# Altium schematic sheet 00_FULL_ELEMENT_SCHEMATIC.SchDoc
size 3600 x 2000 mm
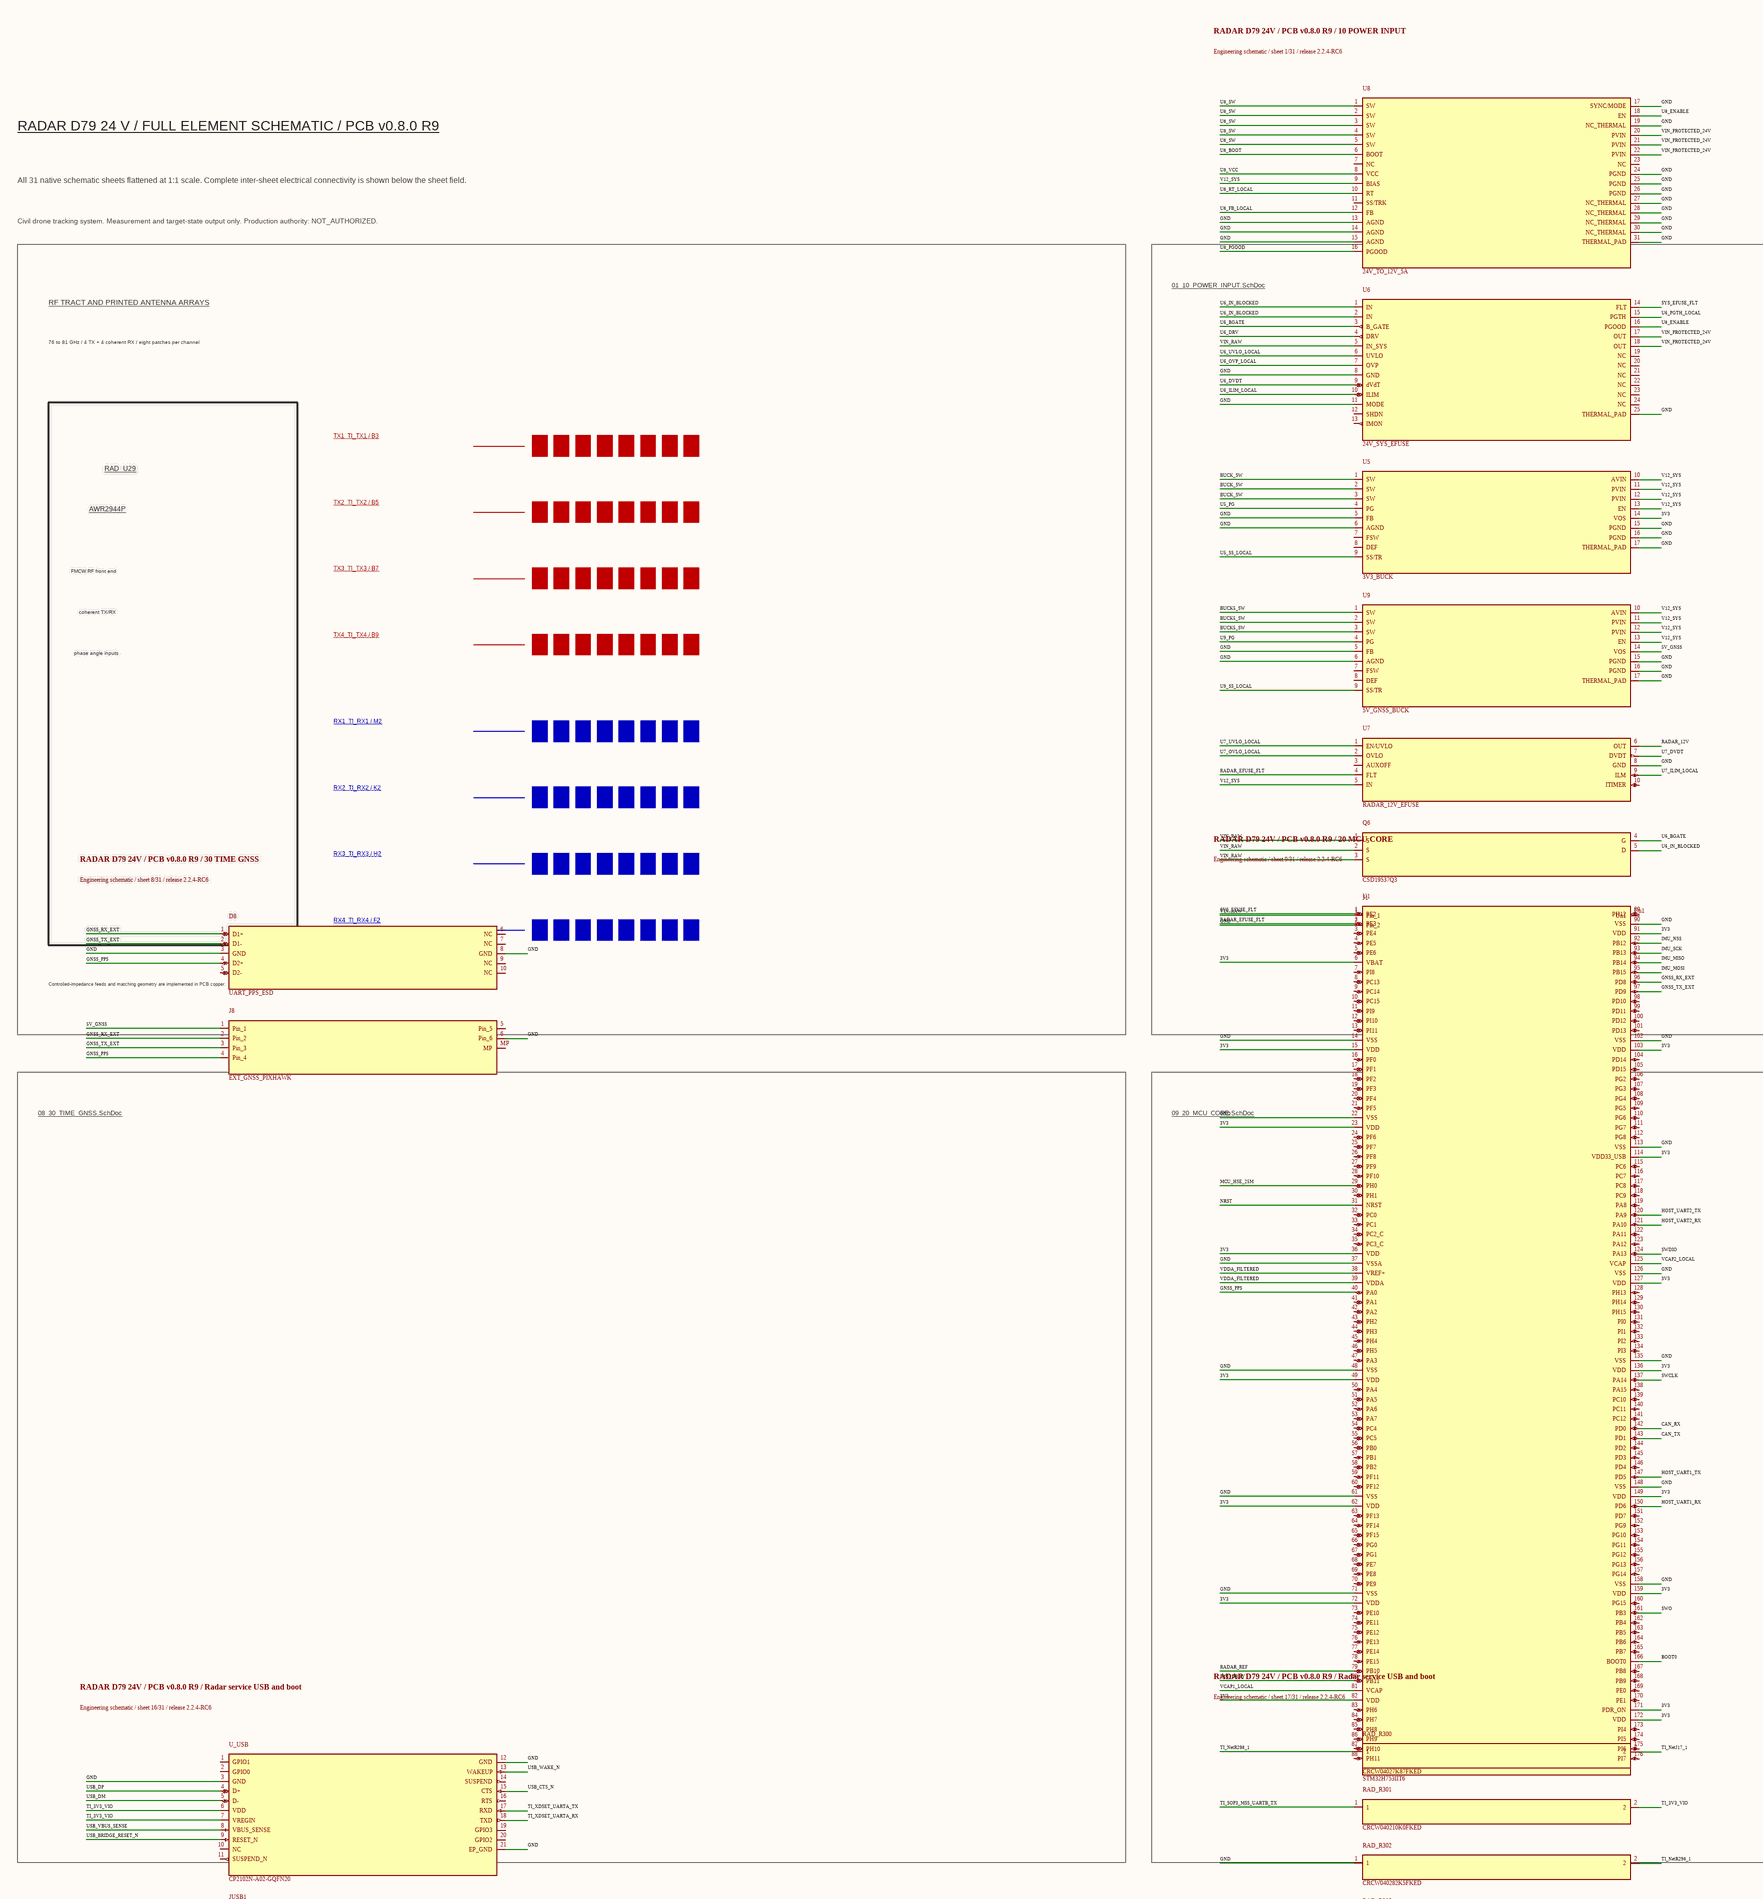
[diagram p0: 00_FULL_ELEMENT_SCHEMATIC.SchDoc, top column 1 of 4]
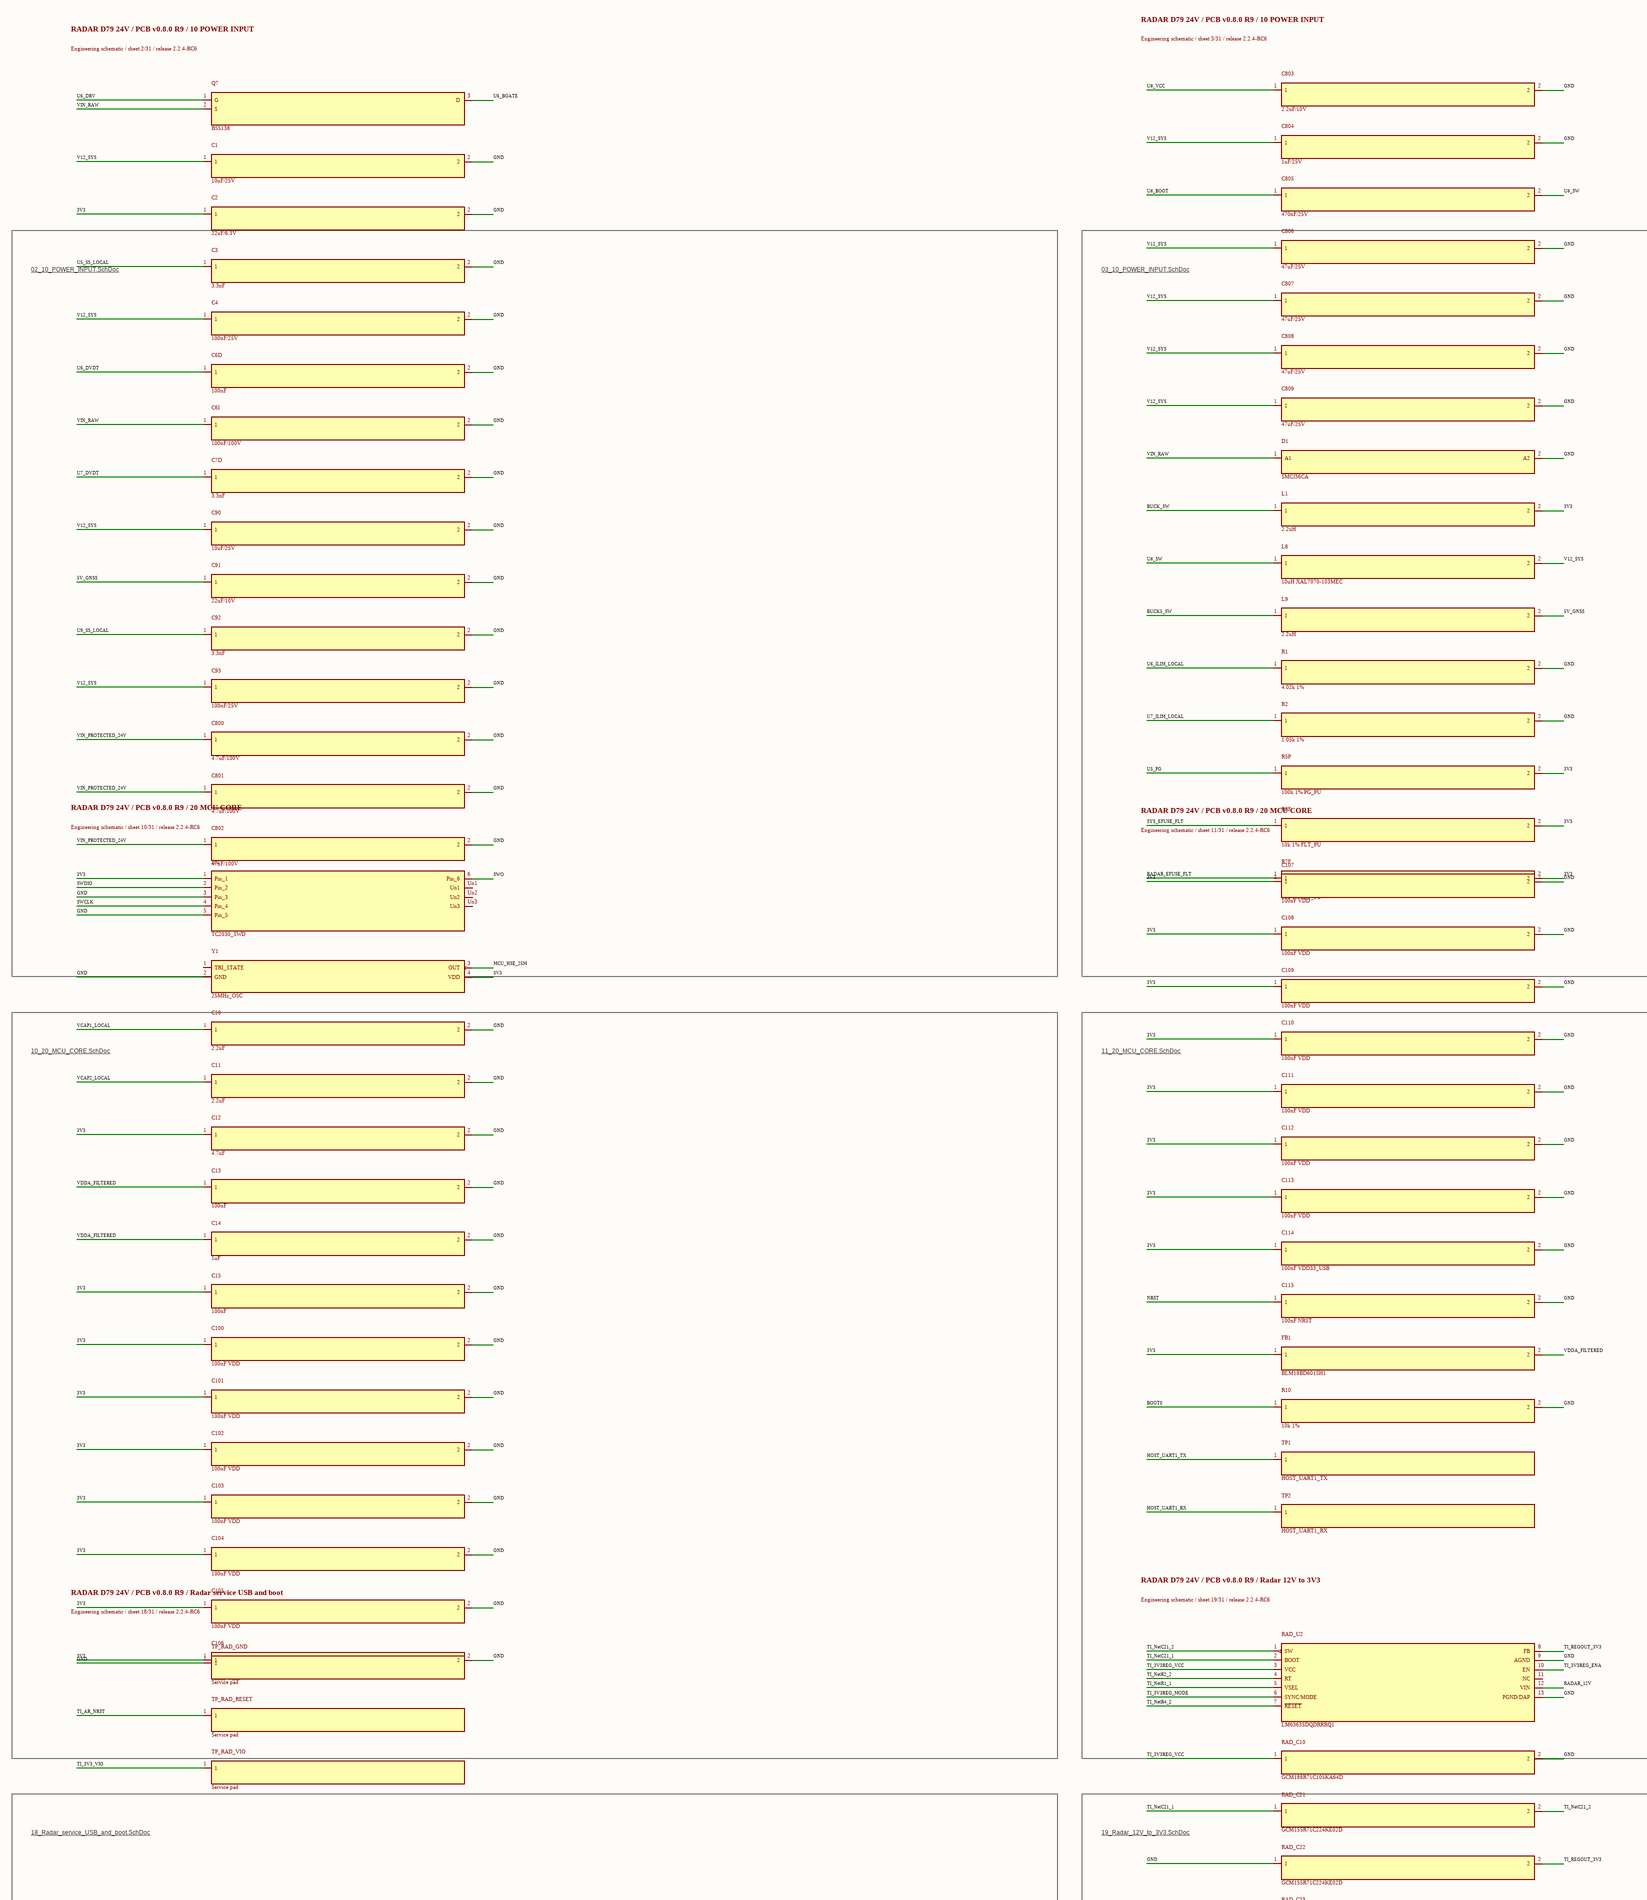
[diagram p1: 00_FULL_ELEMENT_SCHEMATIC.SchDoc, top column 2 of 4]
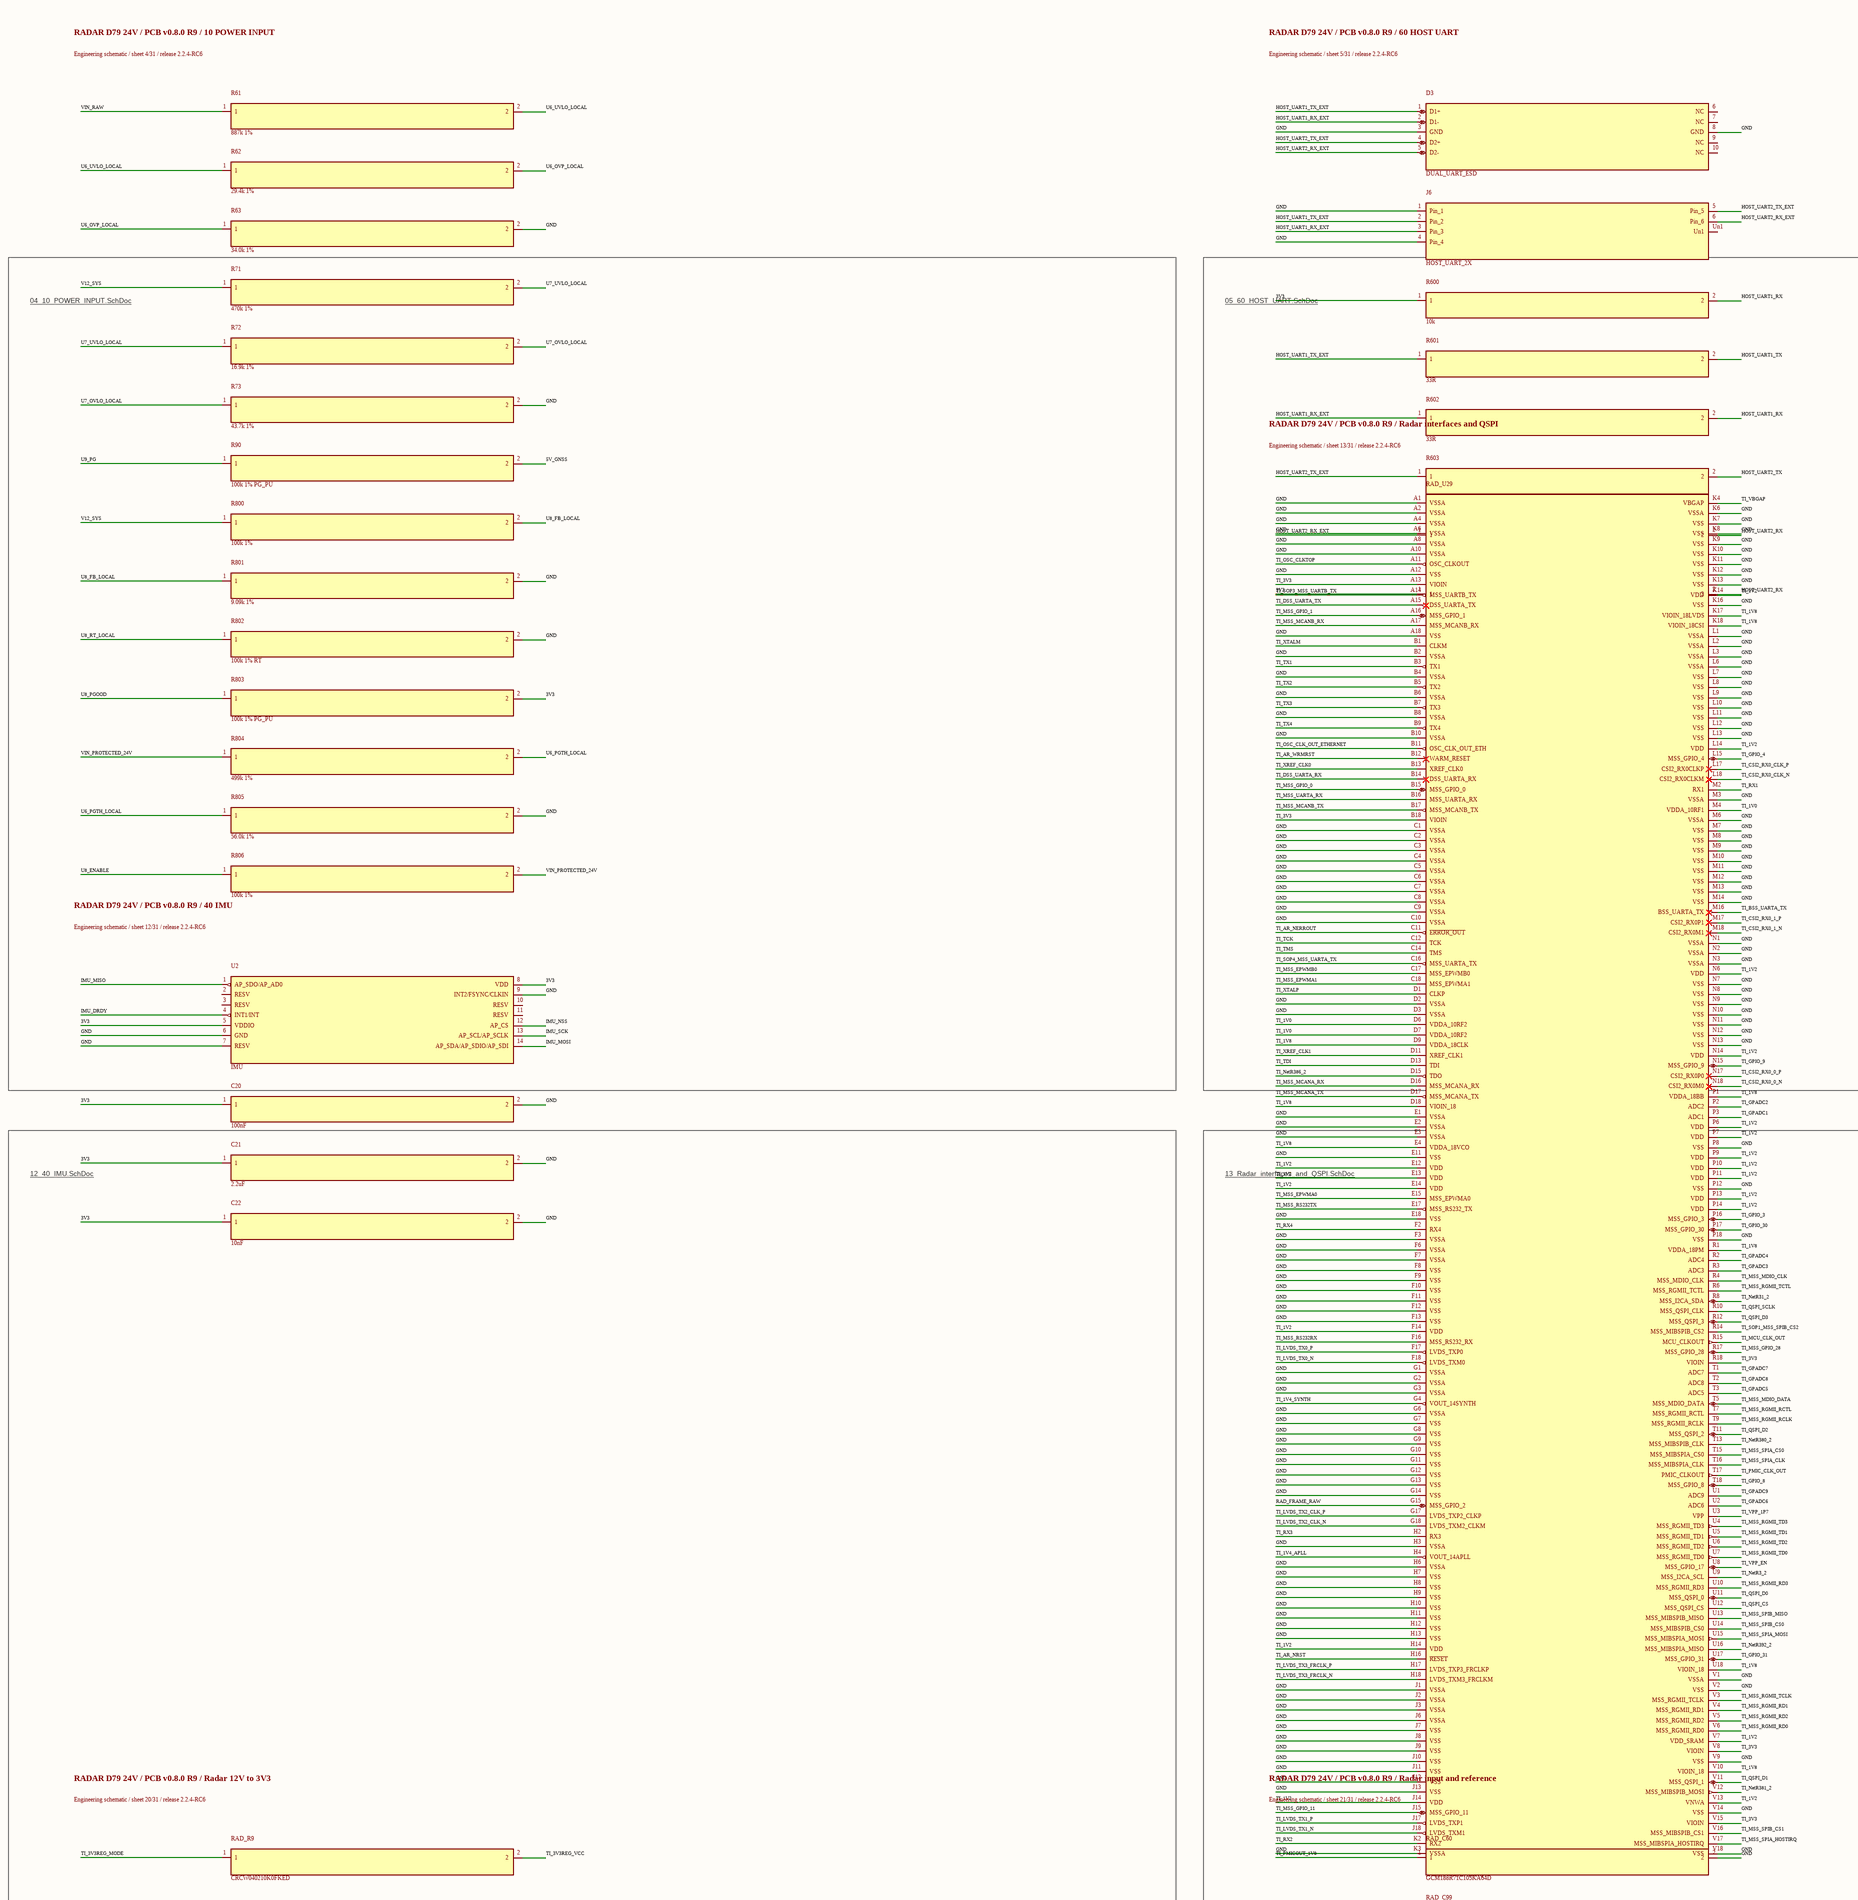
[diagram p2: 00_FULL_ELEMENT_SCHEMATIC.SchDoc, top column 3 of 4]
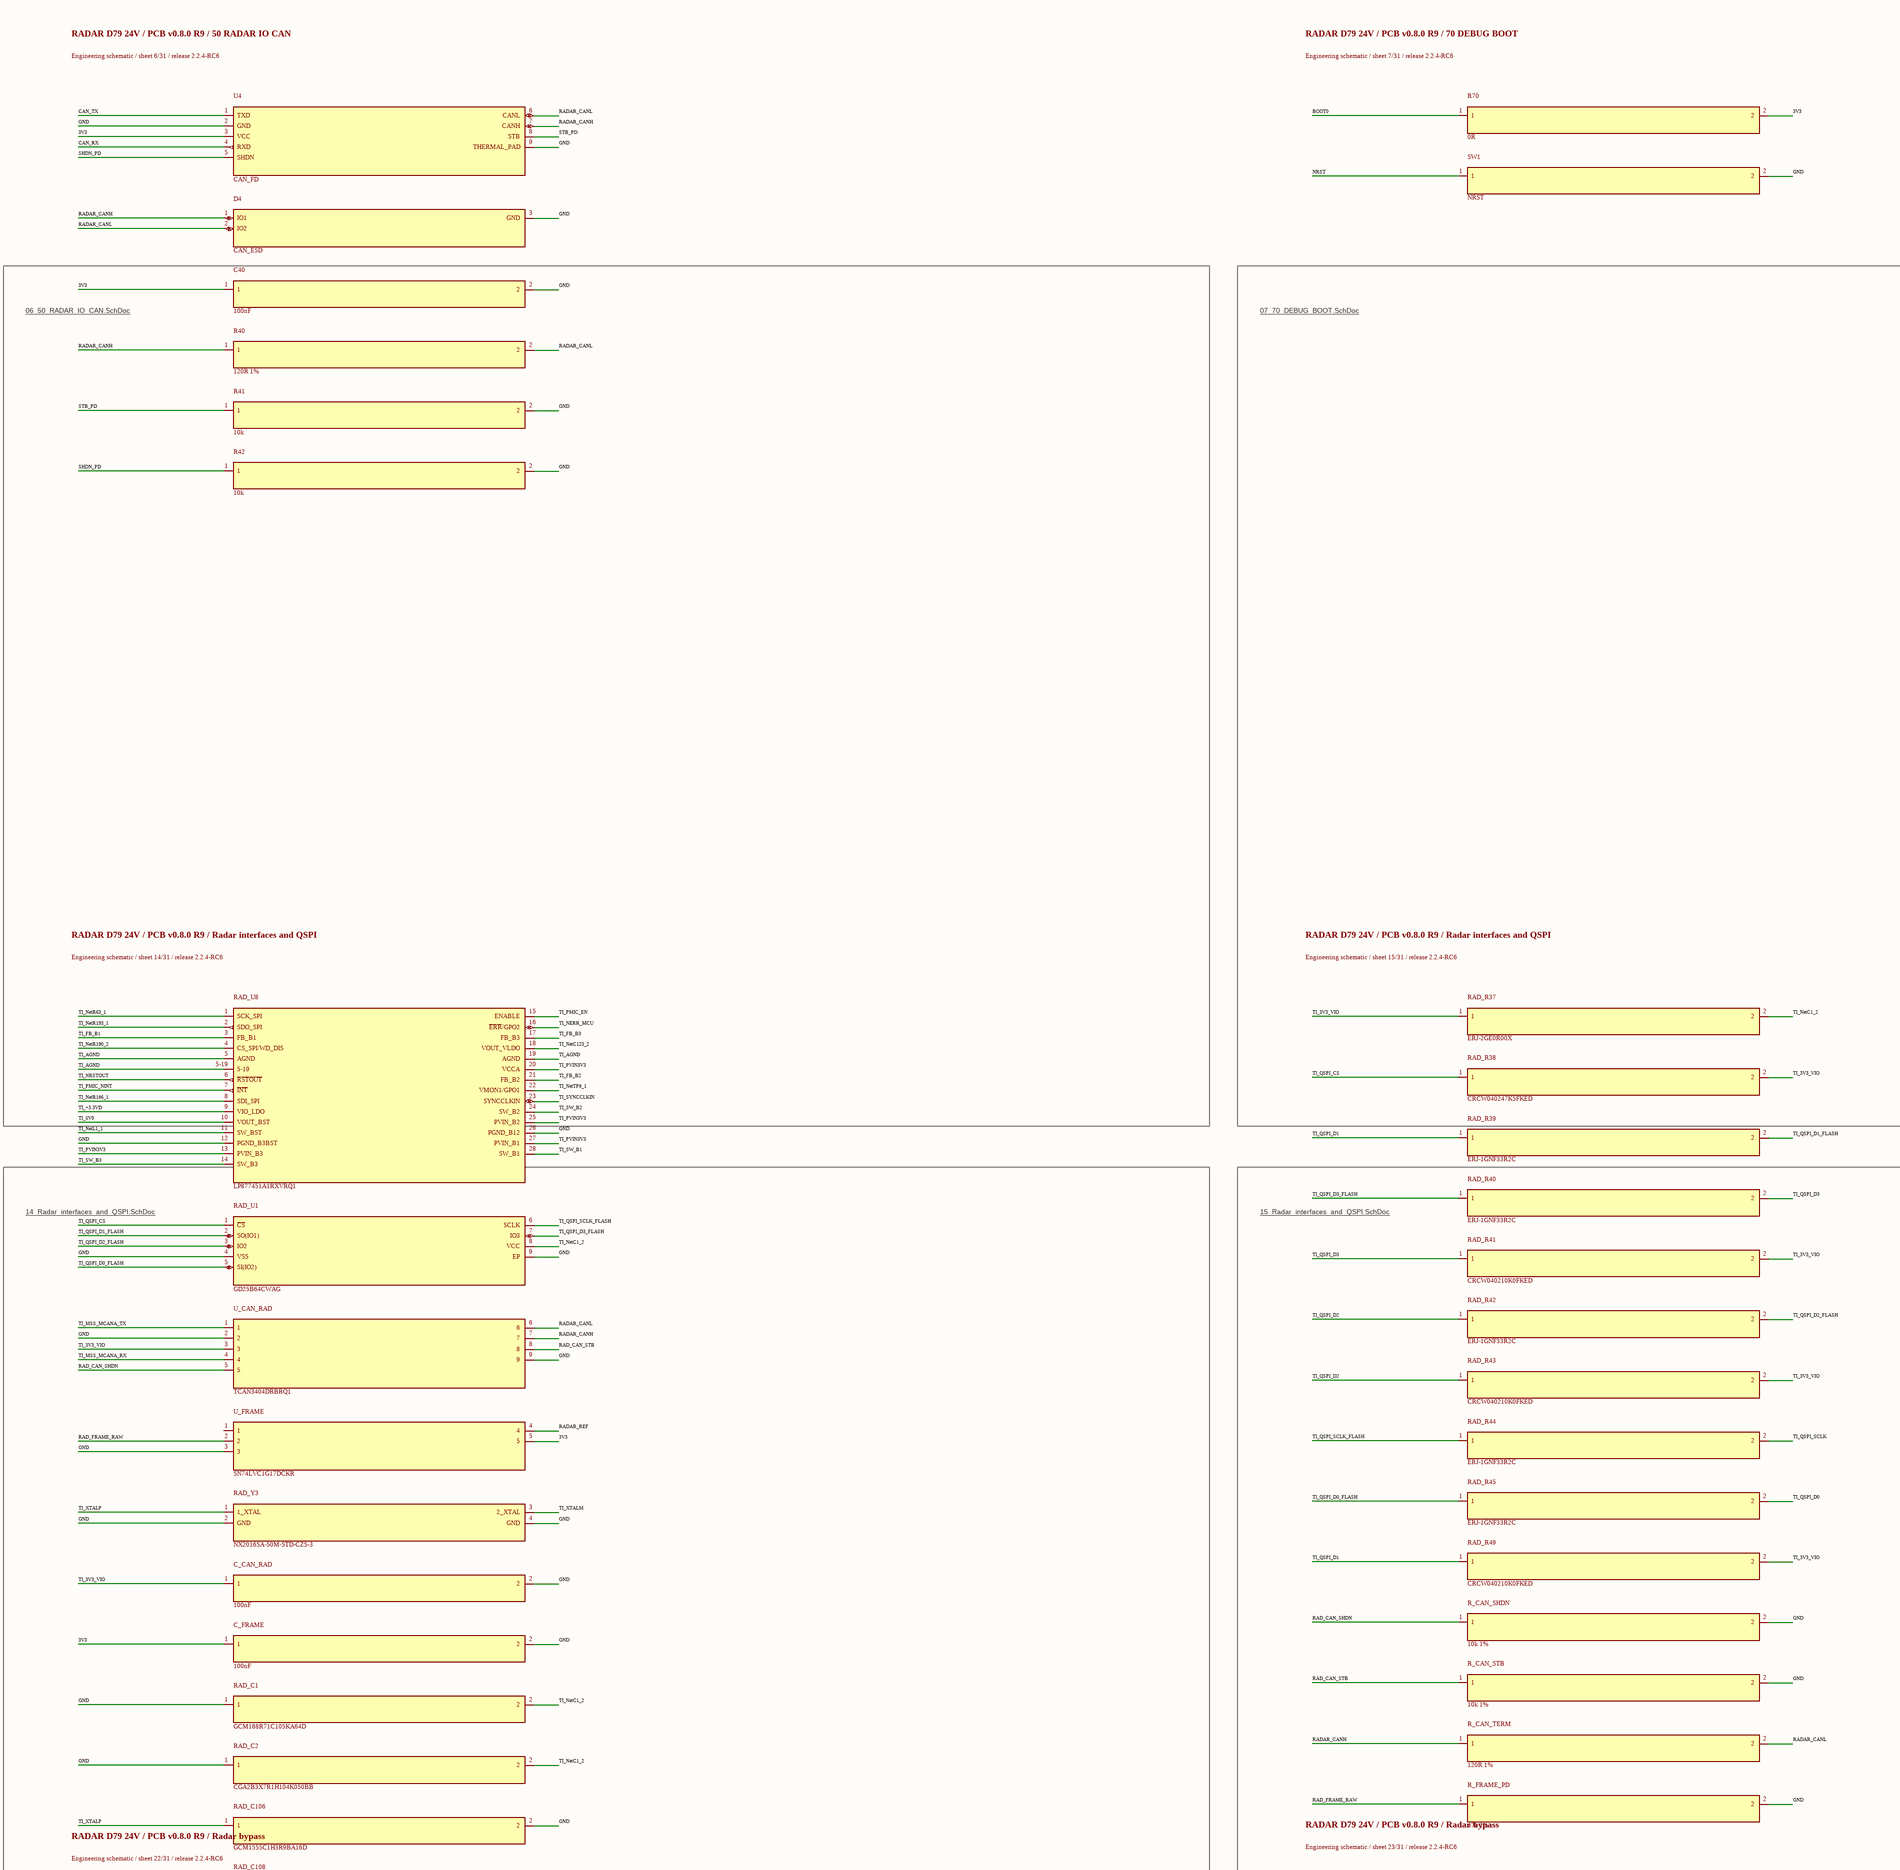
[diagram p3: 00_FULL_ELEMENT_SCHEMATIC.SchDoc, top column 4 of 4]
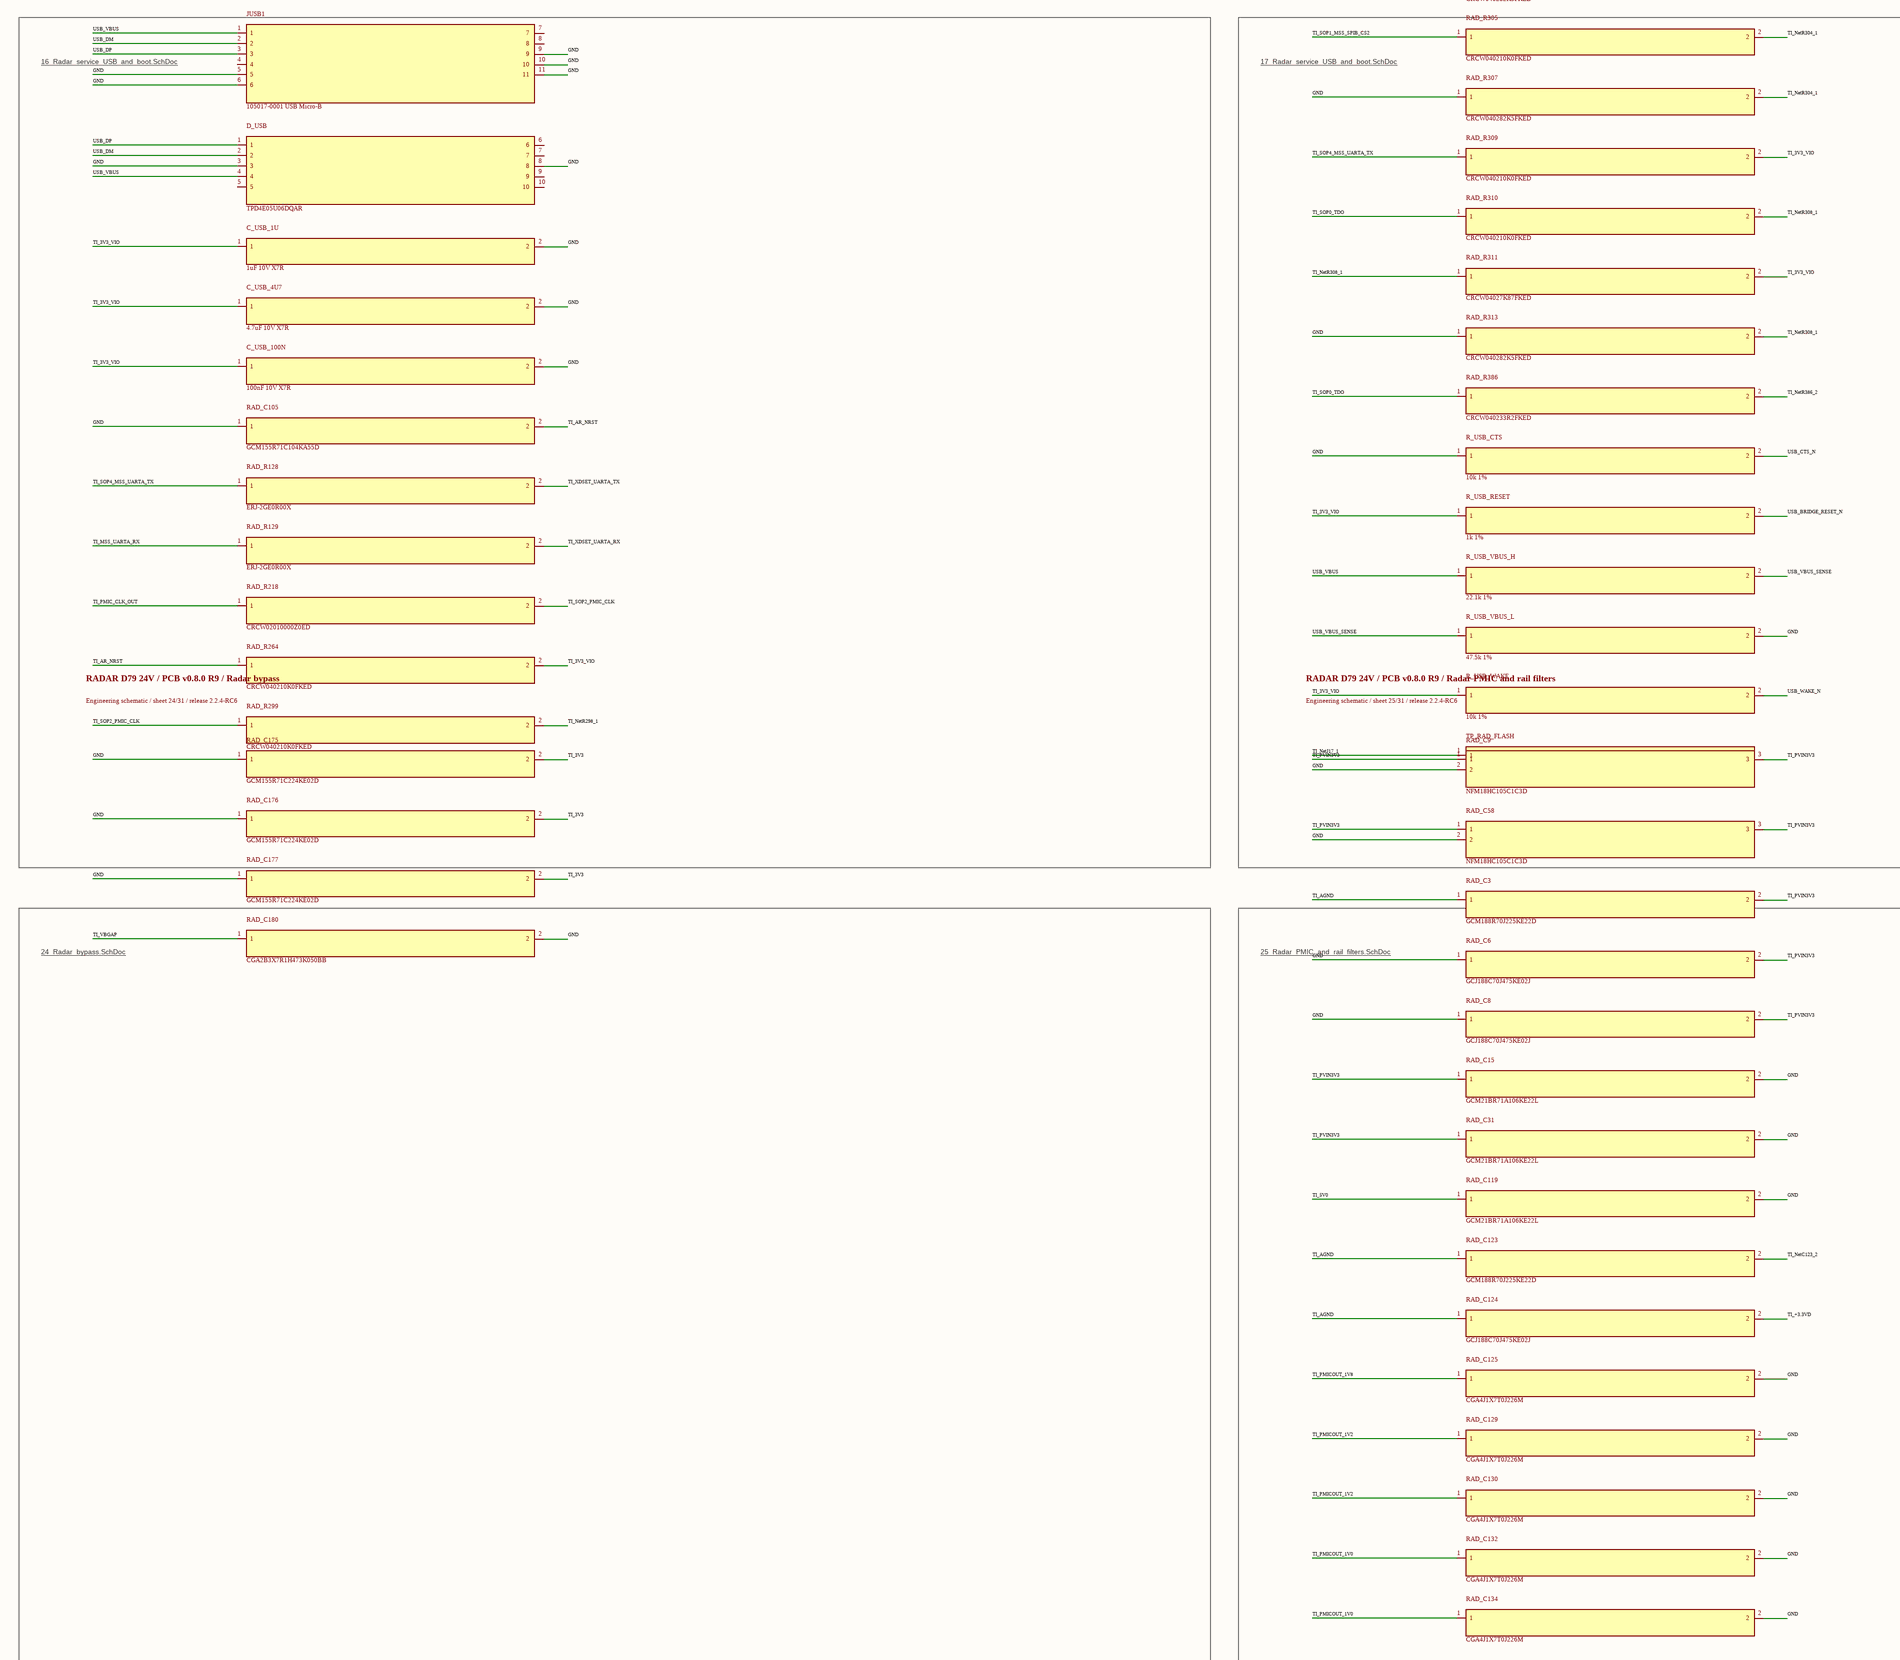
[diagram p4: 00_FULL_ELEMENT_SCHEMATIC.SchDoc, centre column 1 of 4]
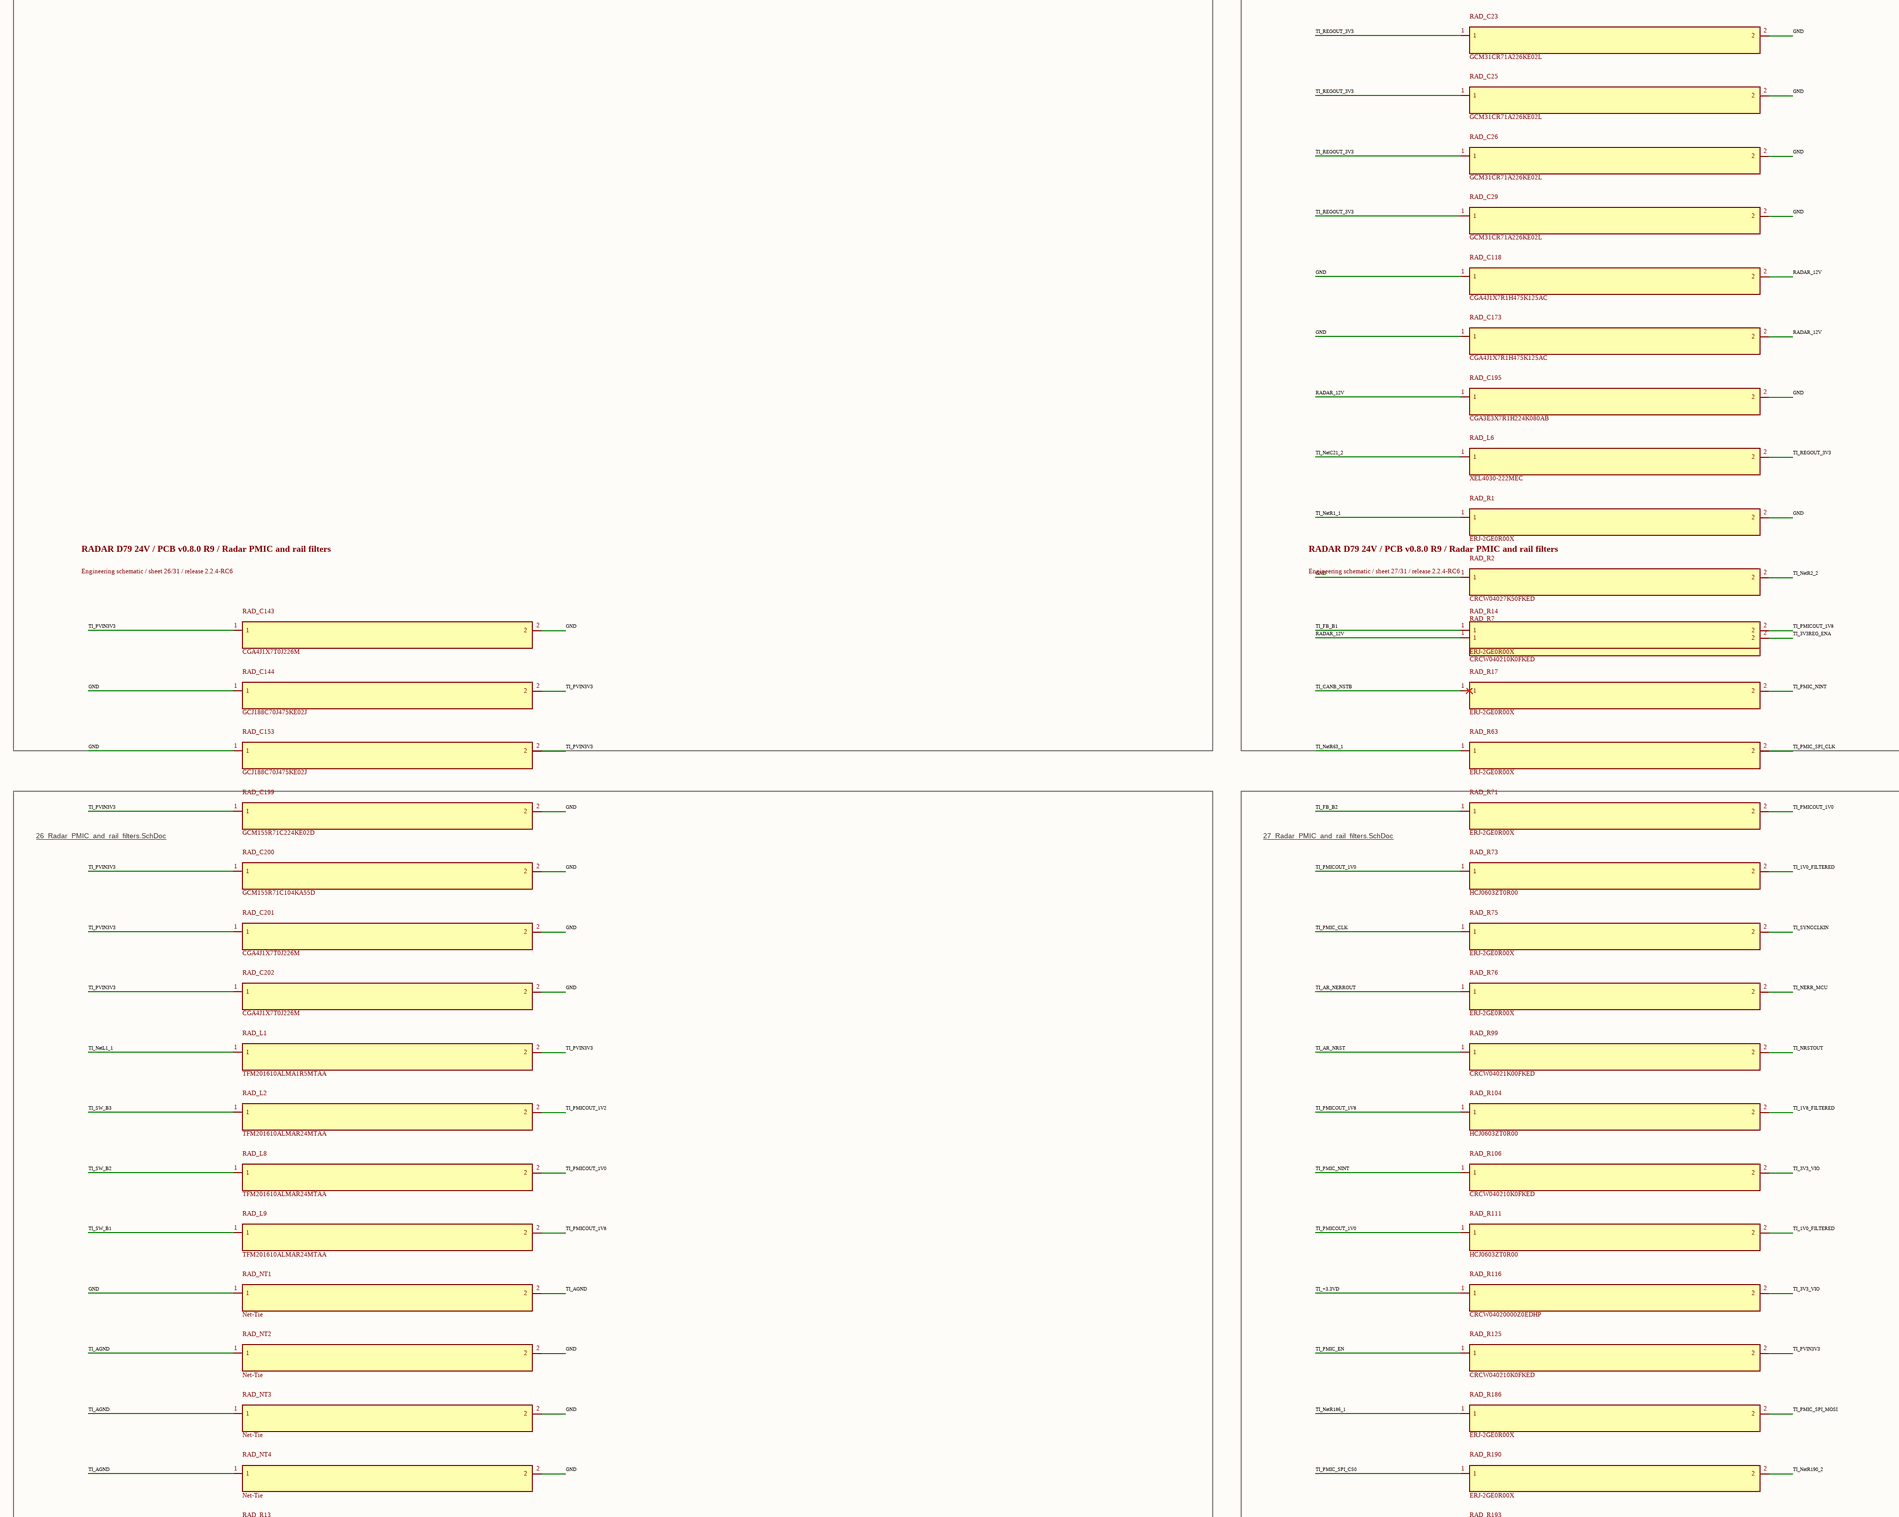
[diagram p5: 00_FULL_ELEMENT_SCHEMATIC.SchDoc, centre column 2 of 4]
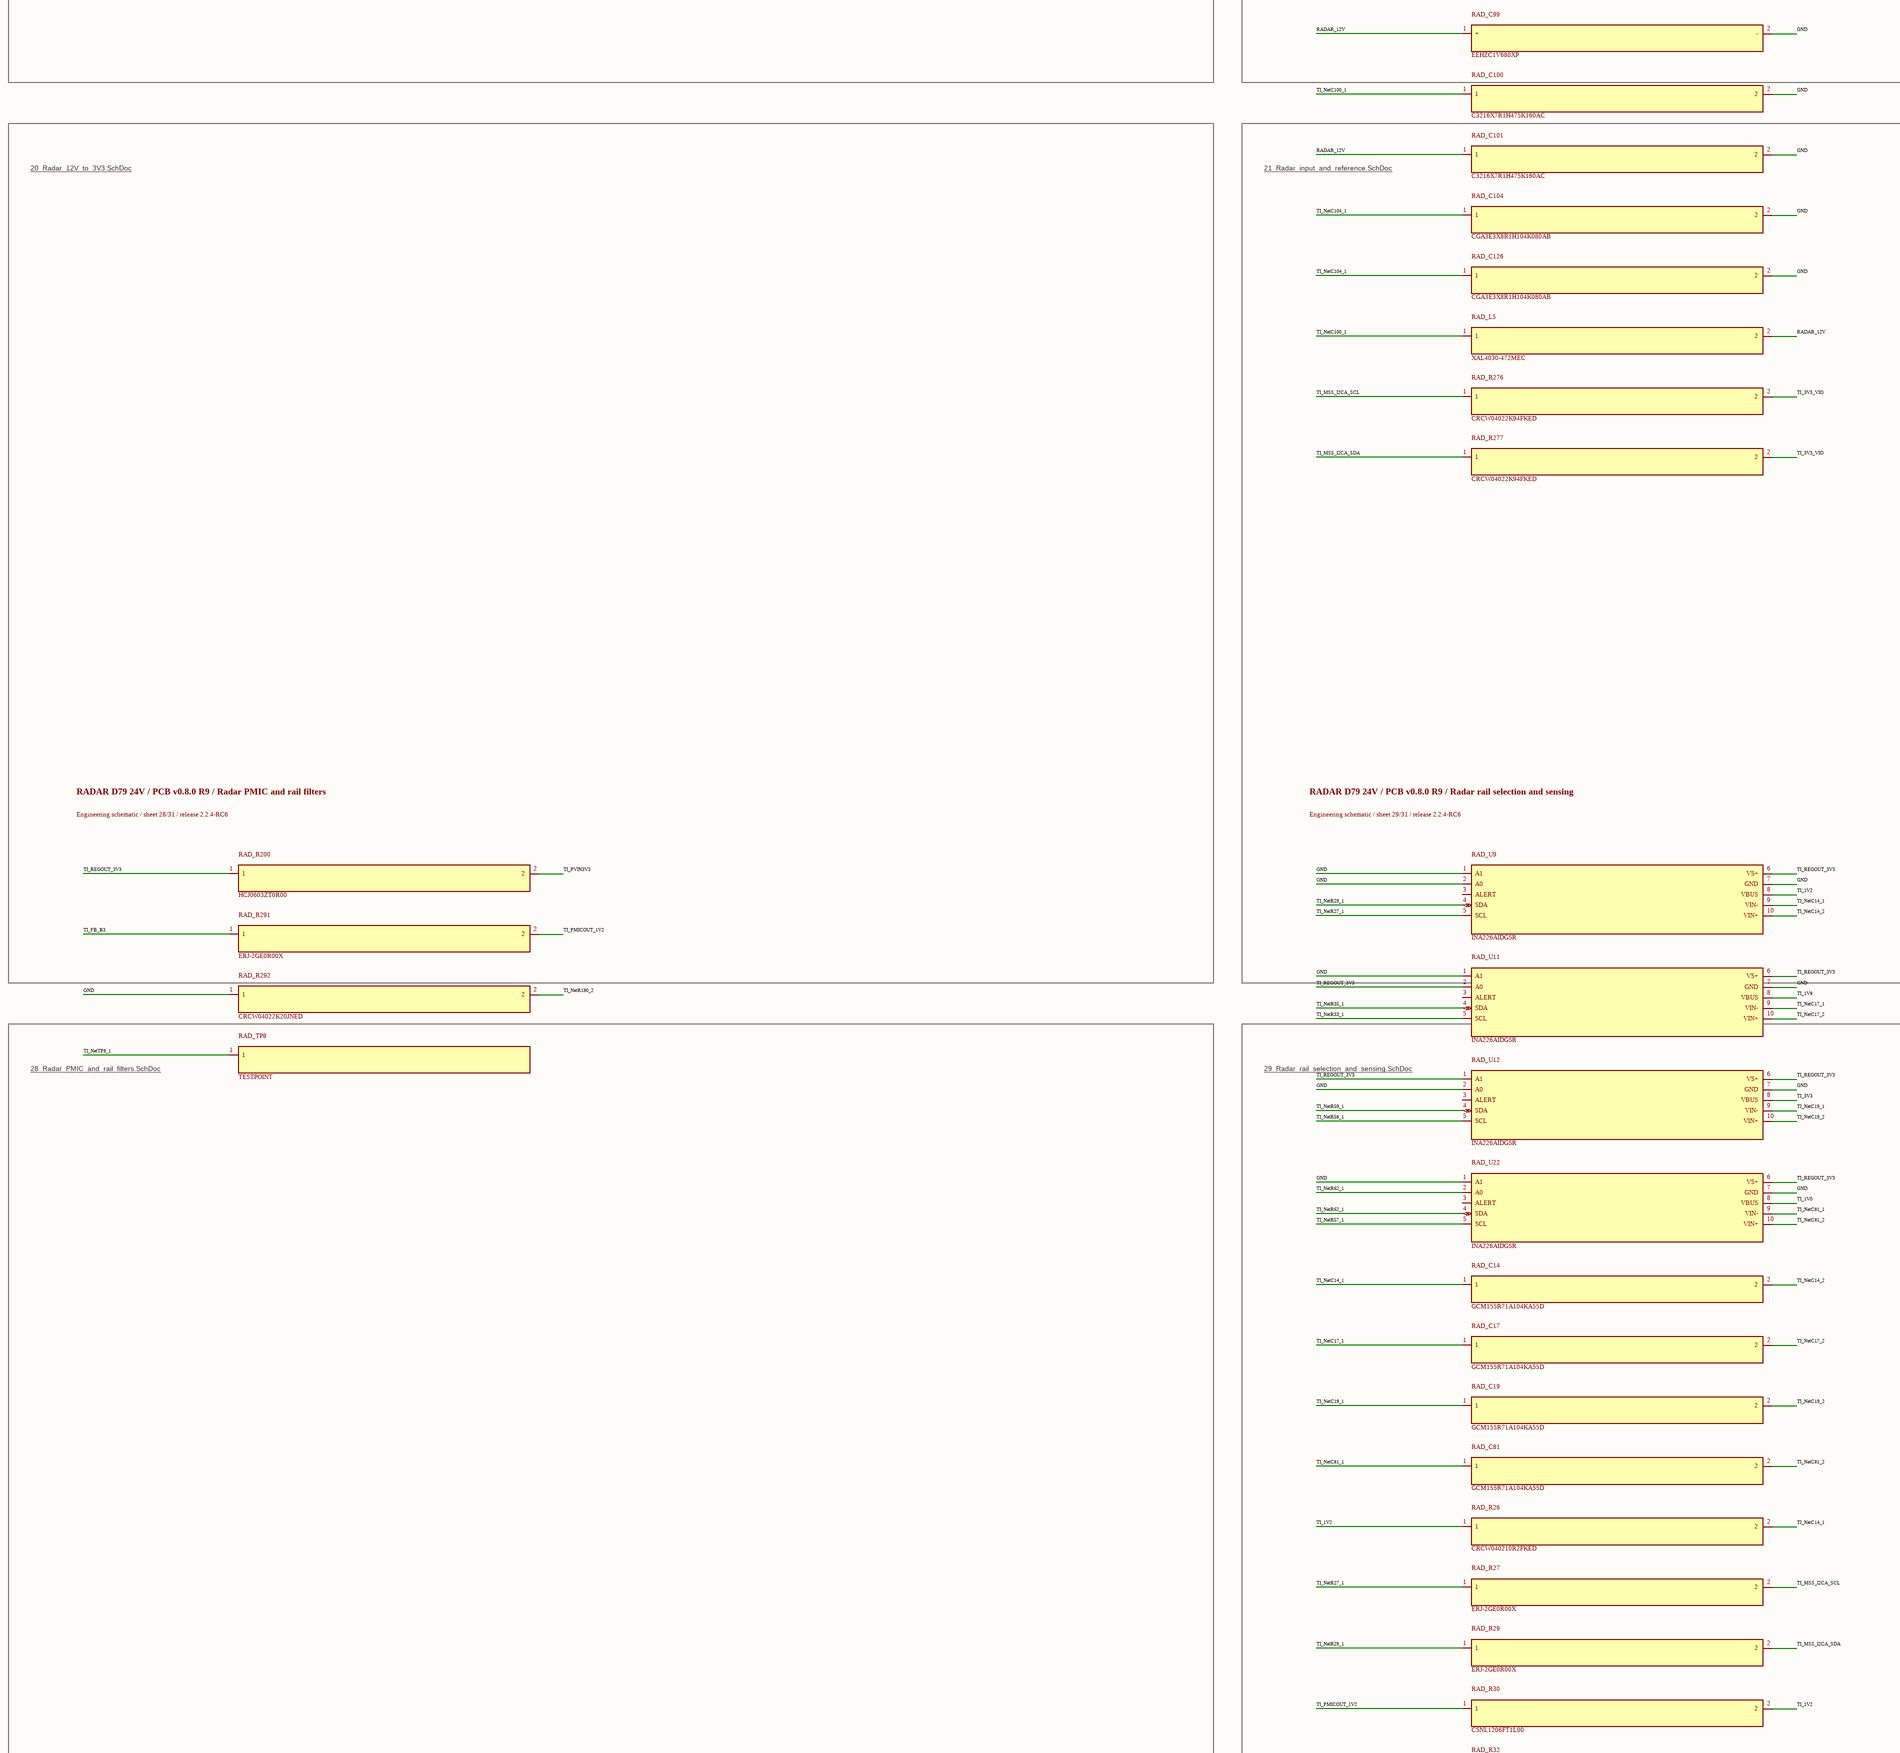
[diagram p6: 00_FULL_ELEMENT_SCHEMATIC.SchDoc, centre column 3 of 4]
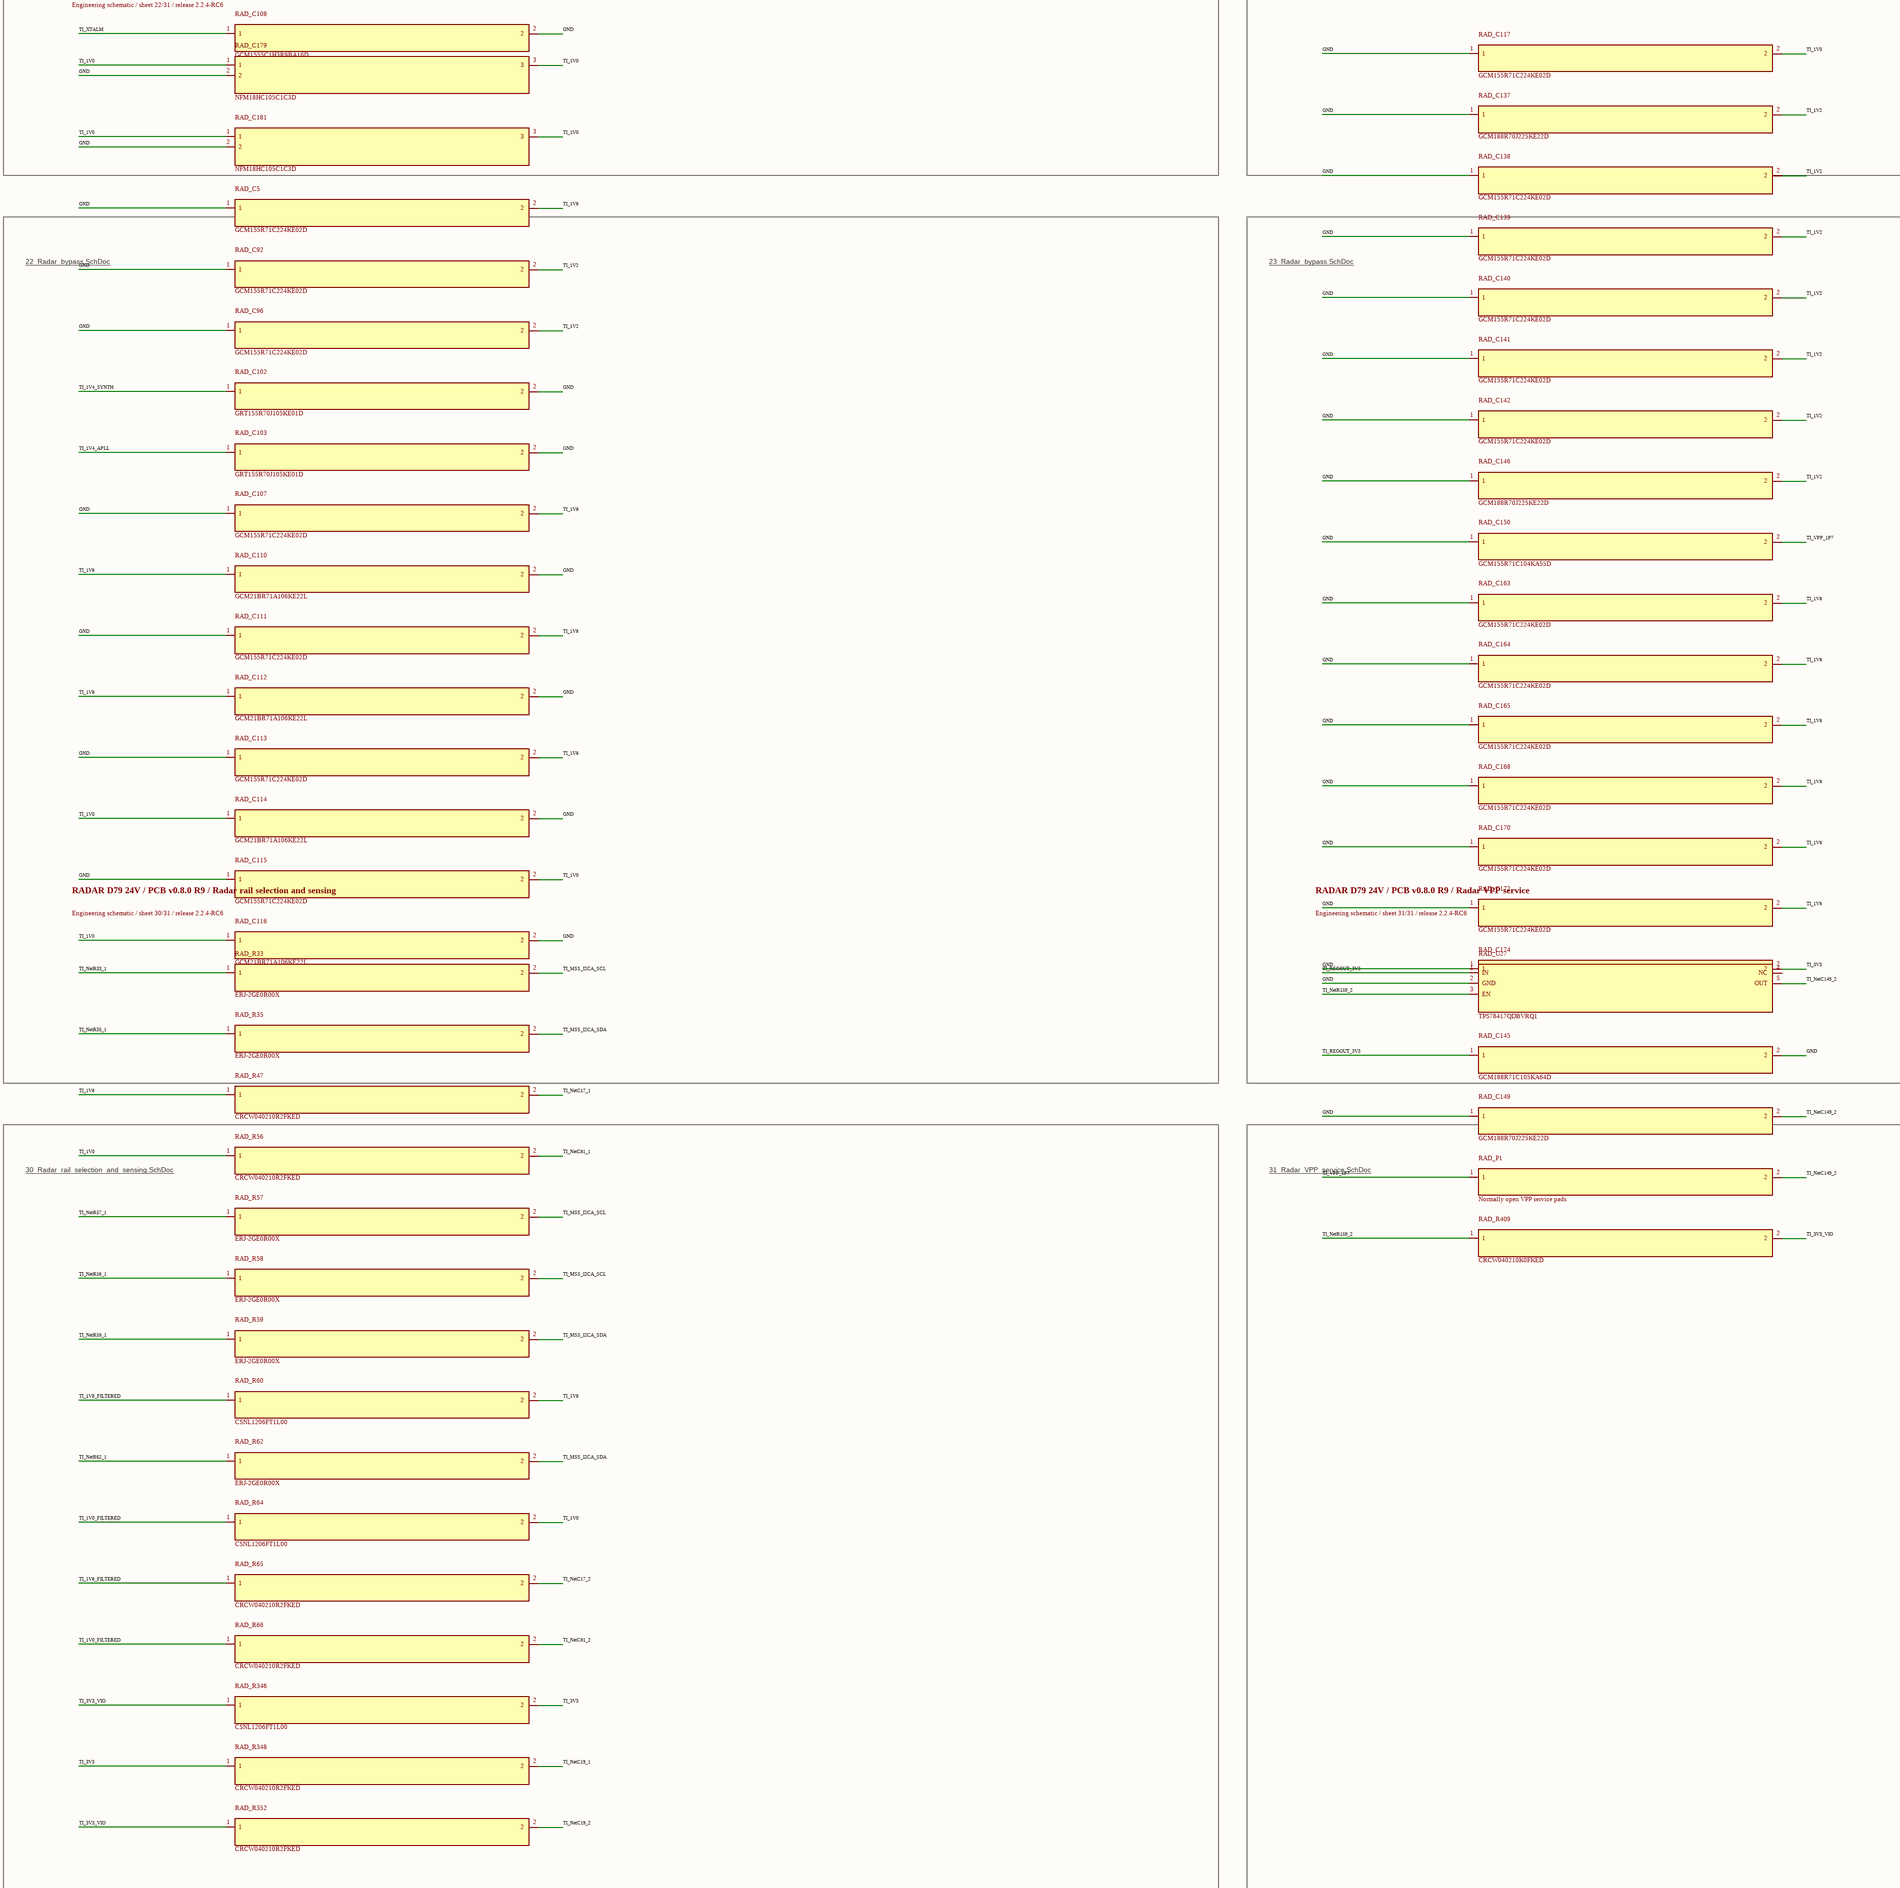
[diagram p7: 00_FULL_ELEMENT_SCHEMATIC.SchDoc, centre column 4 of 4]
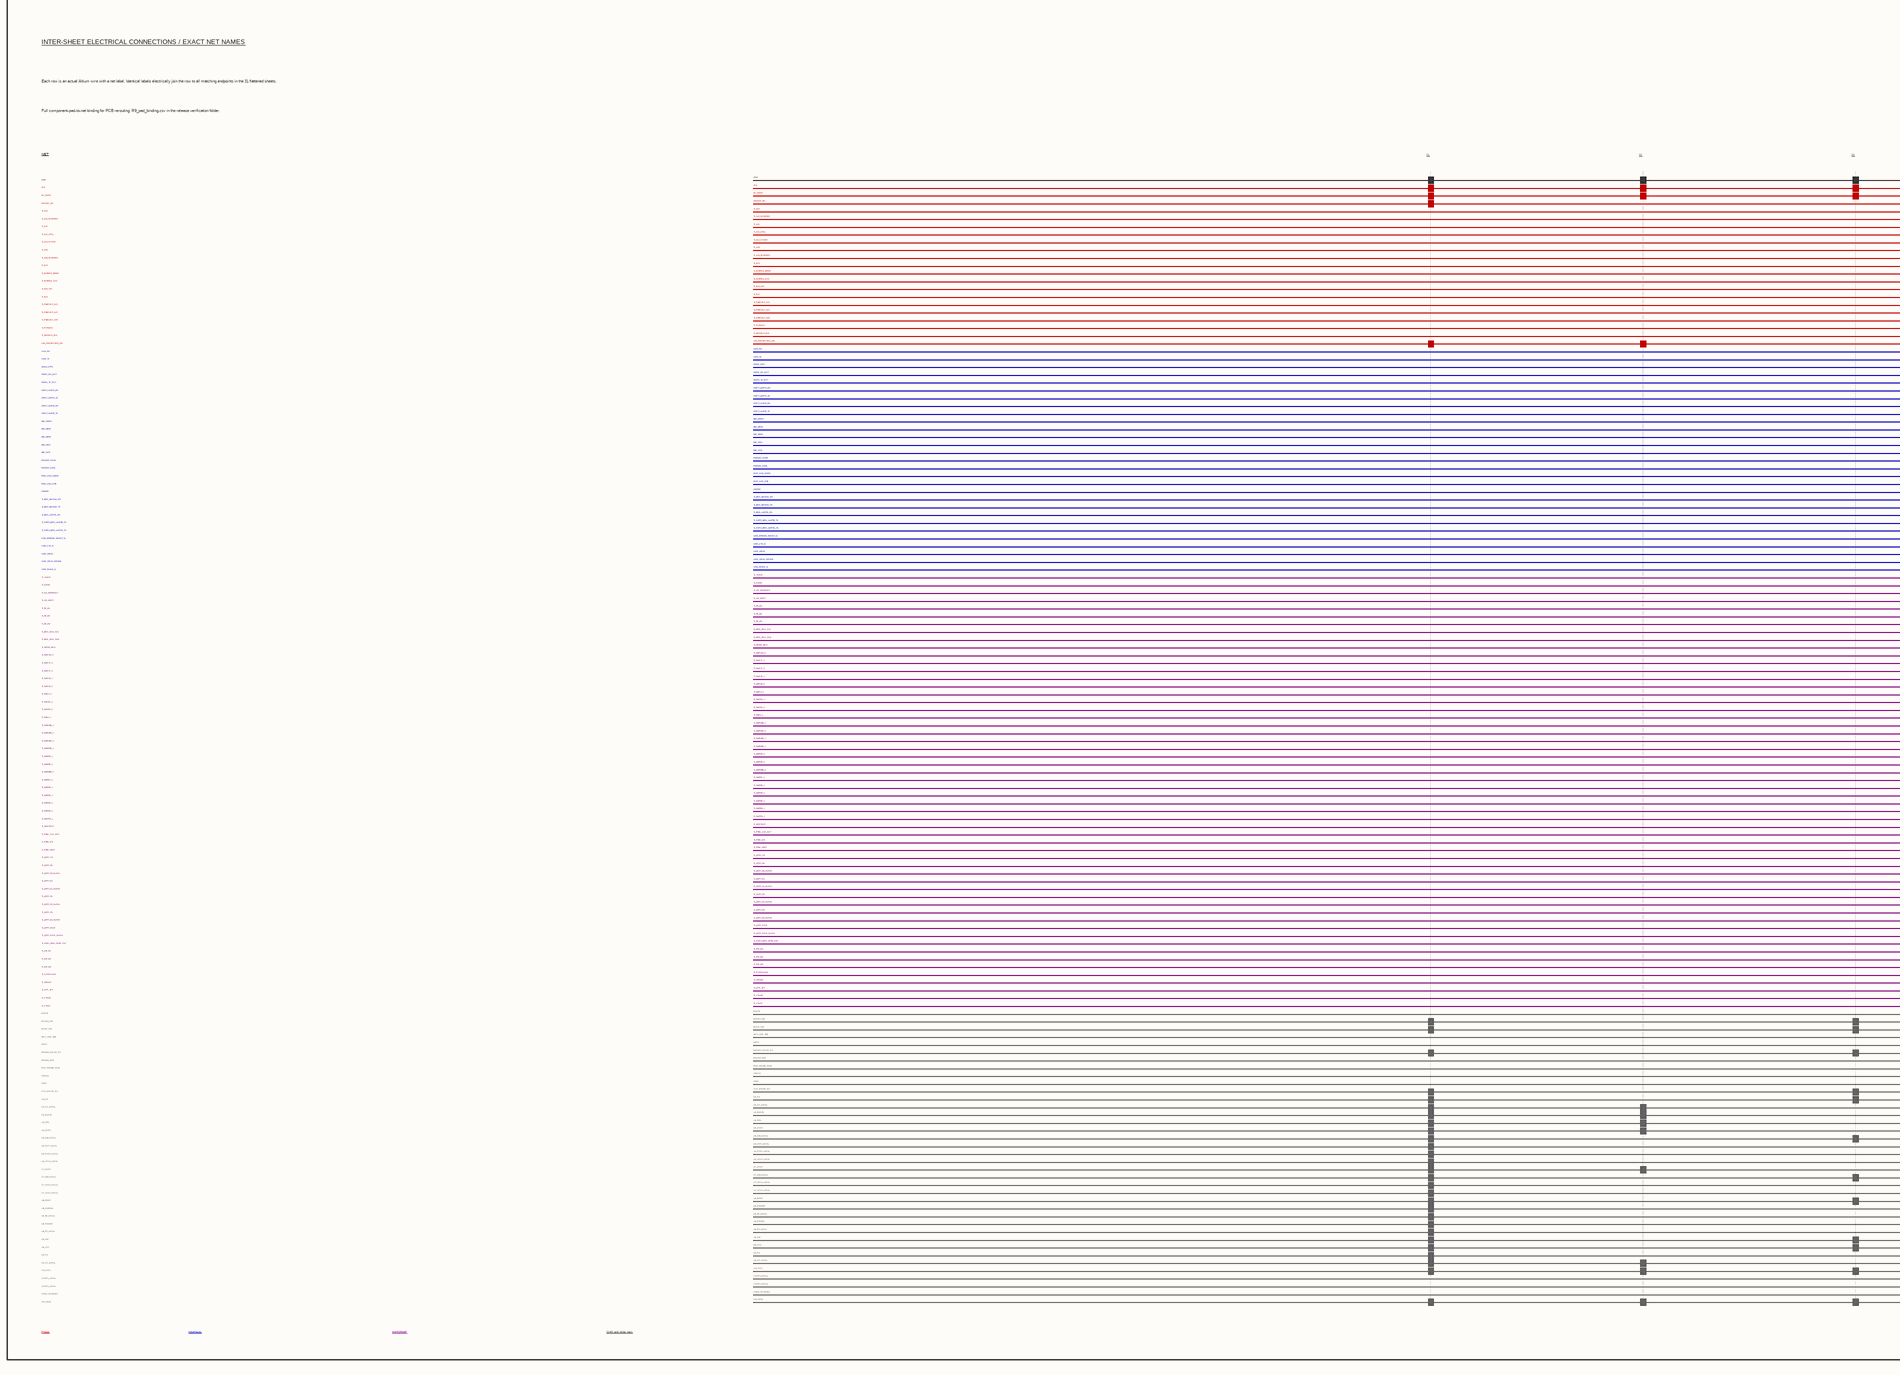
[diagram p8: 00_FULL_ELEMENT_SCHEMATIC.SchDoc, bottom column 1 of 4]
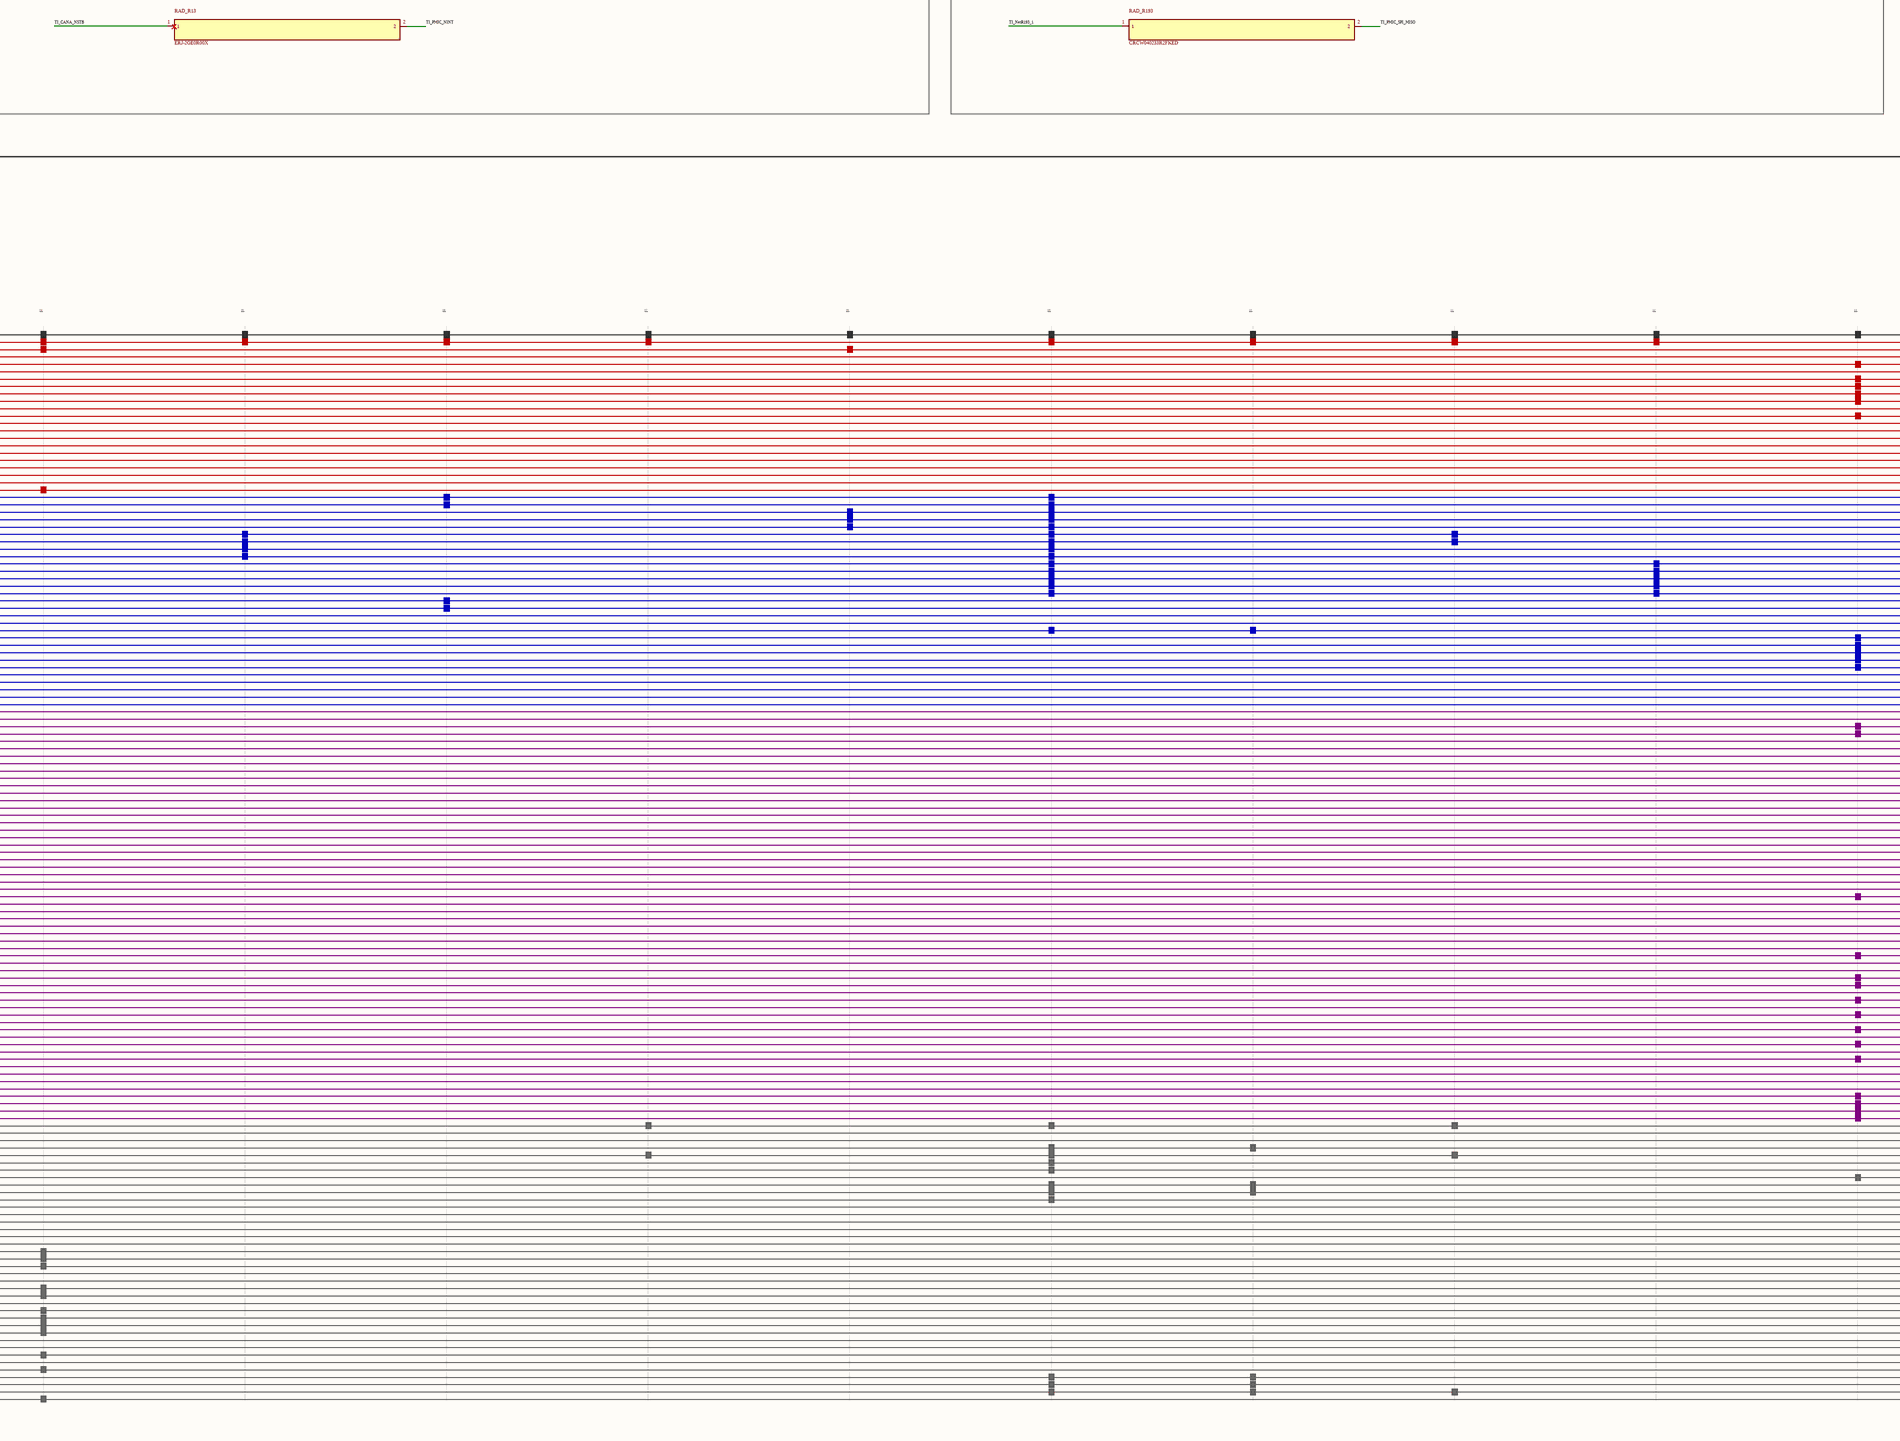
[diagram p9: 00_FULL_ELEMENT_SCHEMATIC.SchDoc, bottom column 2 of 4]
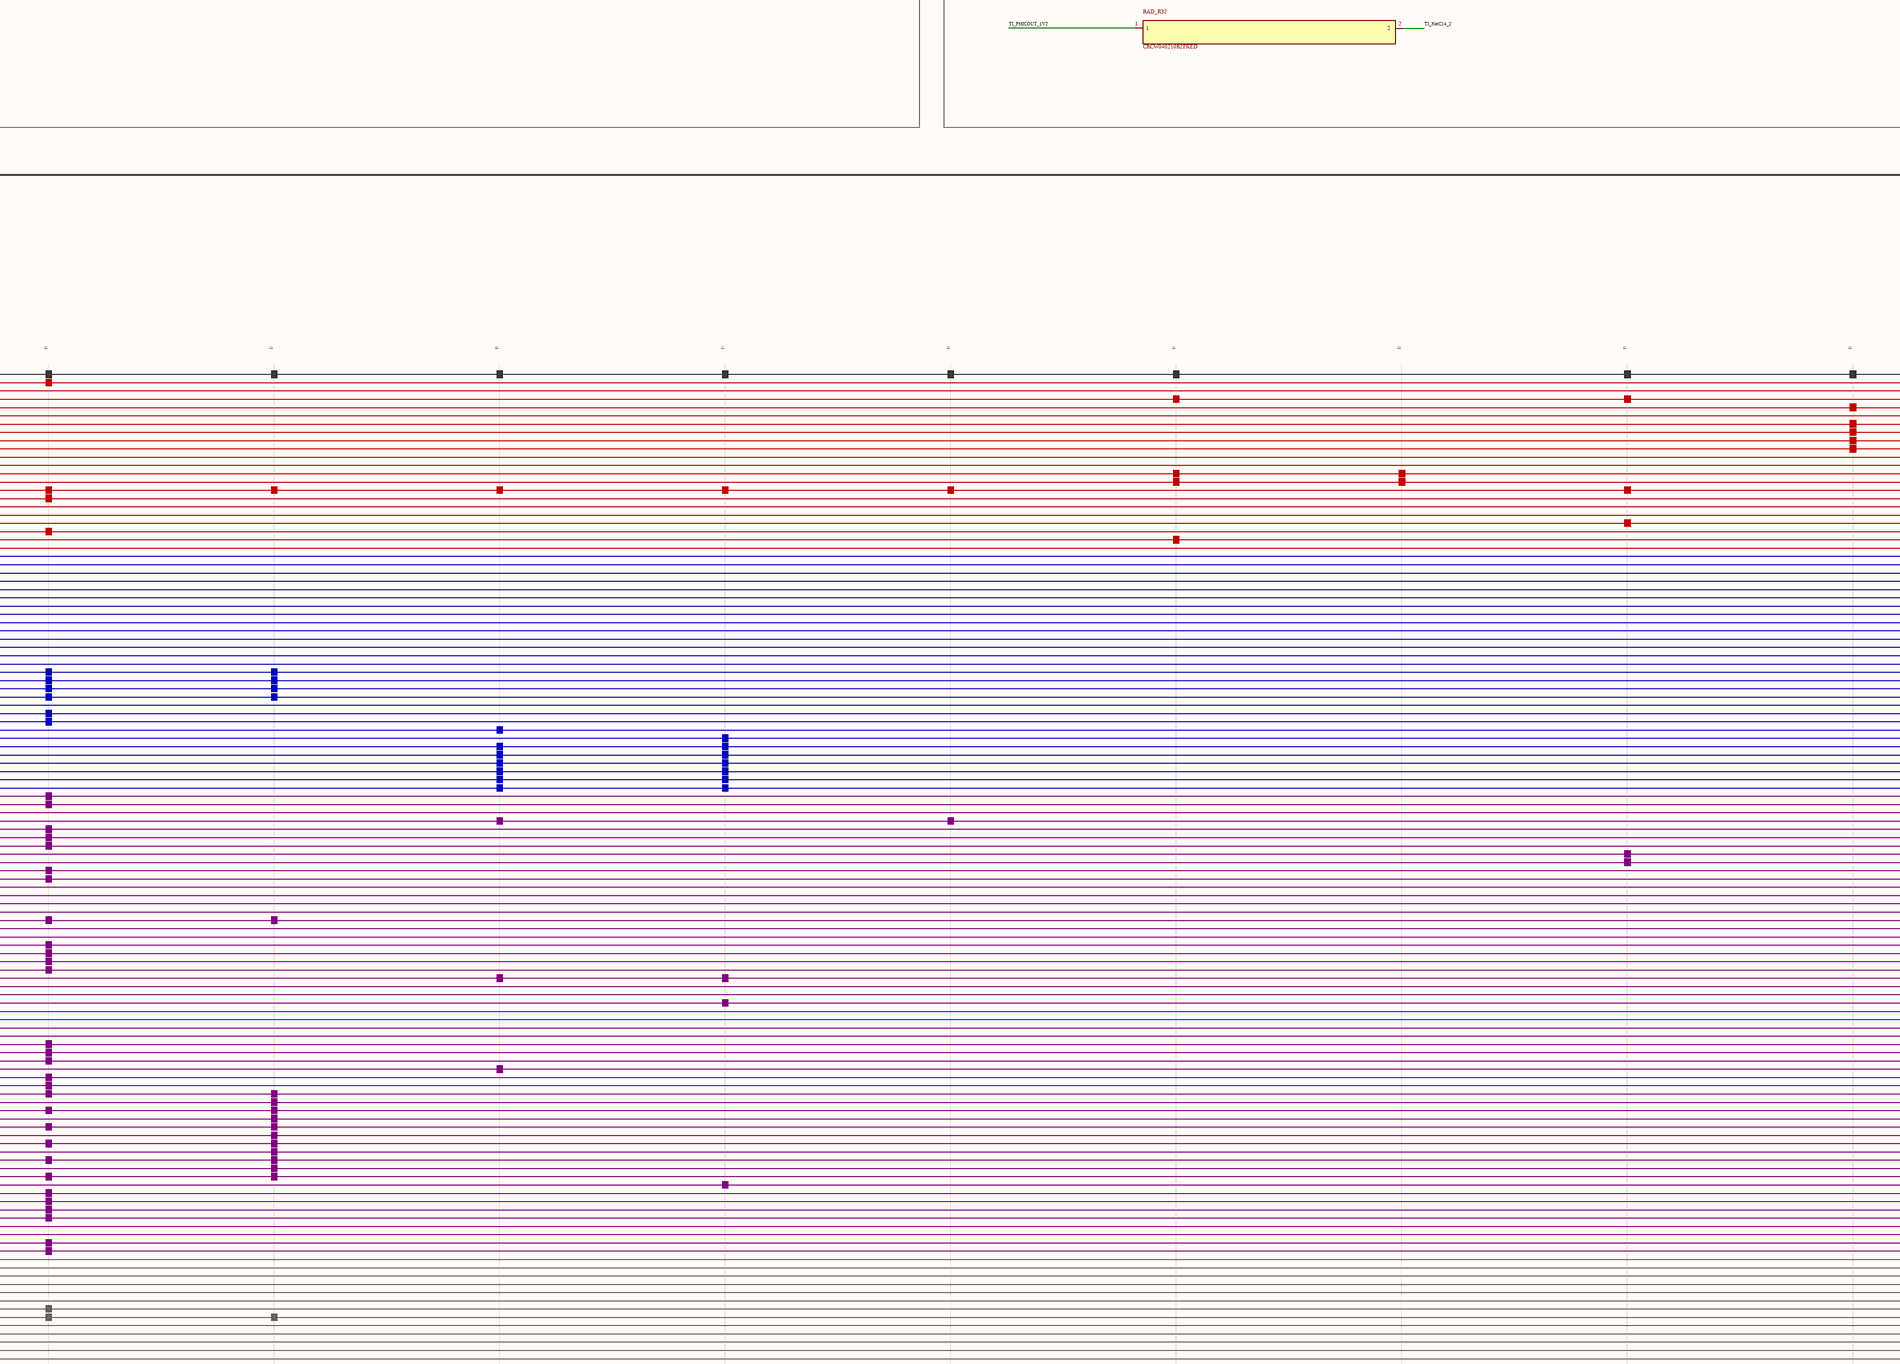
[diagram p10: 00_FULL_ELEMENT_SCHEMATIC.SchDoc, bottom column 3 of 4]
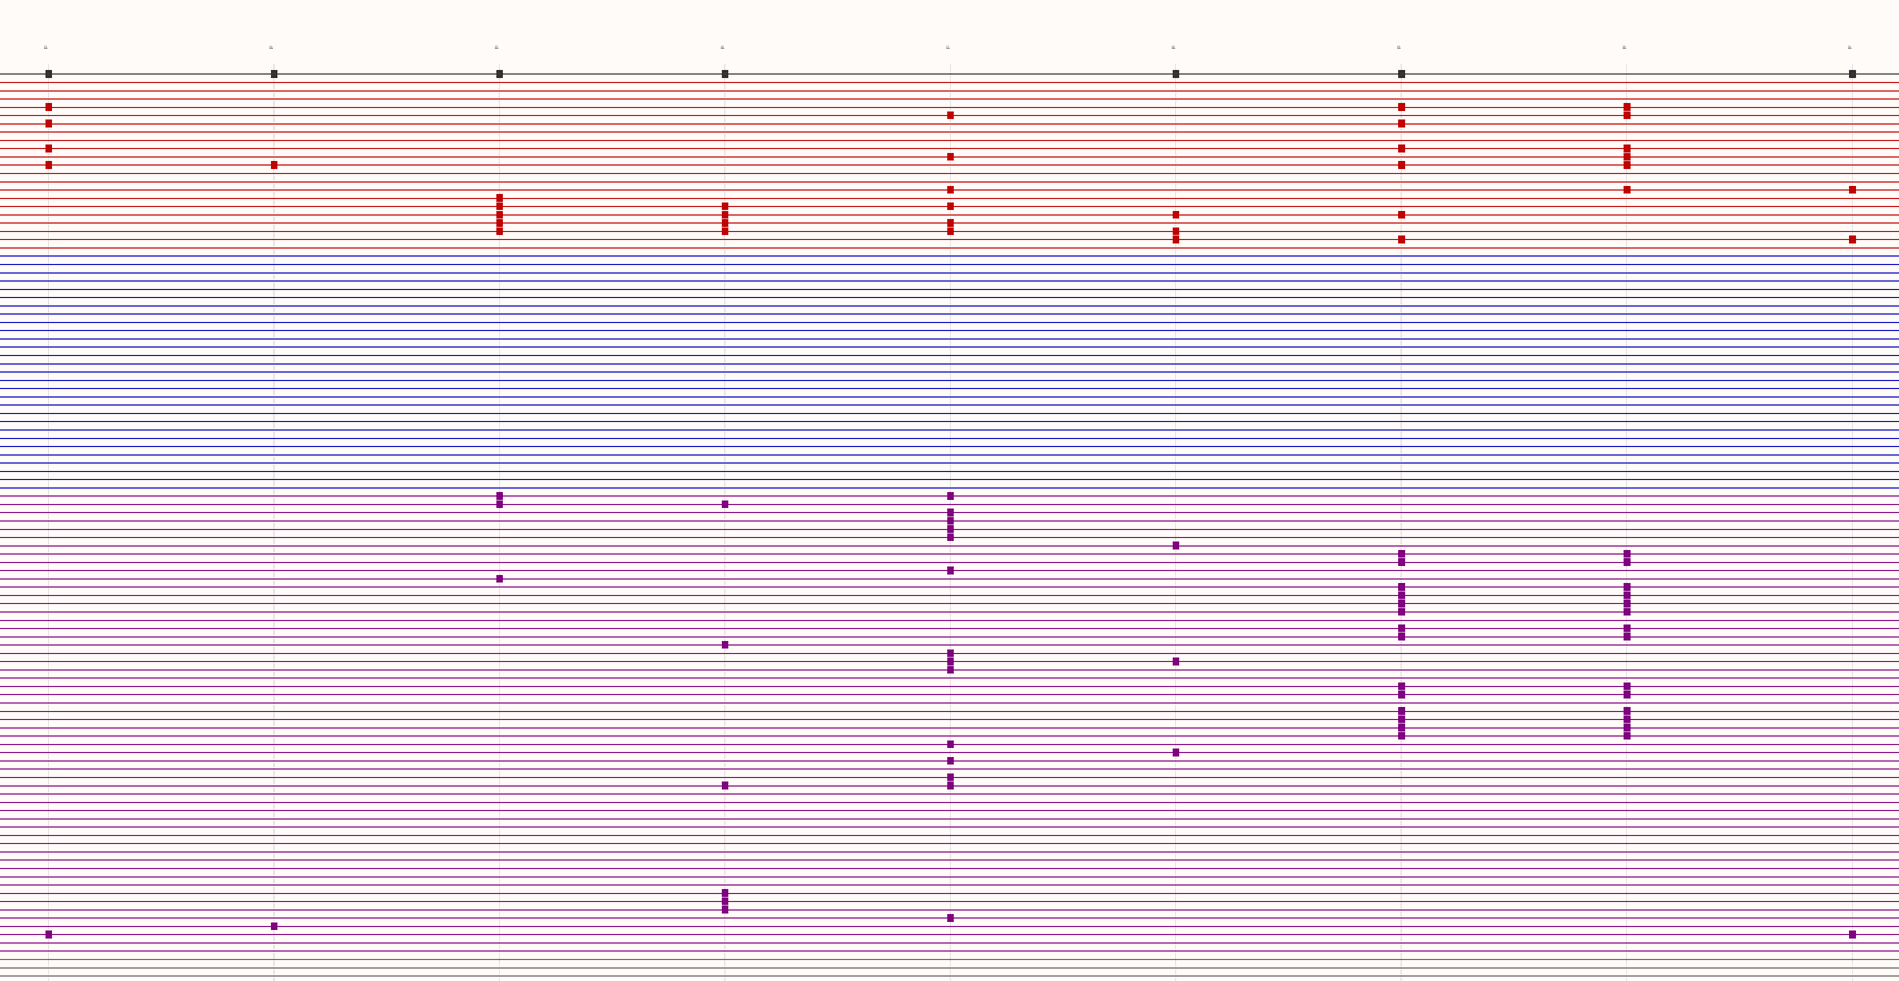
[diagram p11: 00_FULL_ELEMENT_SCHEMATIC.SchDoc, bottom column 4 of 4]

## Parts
C1  10uF/25V  [C_1206_3216Metric]
C2  22uF/6.3V  [C_1206_3216Metric]
C3  3.3nF  [C_0603_1608Metric]
C4  100nF/25V  [C_0603_1608Metric]
C6D  100nF  [C_0603_1608Metric]
C6I  100nF/100V  [C_0603_1608Metric]
C7D  3.3nF  [C_0603_1608Metric]
C10  2.2uF  [C_0603_1608Metric]
C11  2.2uF  [C_0603_1608Metric]
C12  4.7uF  [C_0805_2012Metric]
C13  100nF  [C_0402_1005Metric]
C14  1uF  [C_0603_1608Metric]
C15  100nF  [C_0402_1005Metric]
C20  100nF  [C_0402_1005Metric]
C21  2.2uF  [C_0603_1608Metric]
C22  10nF  [C_0402_1005Metric]
C40  100nF  [C_0402_1005Metric]
C90  10uF/25V  [C_1206_3216Metric]
C91  22uF/10V  [C_1206_3216Metric]
C92  3.3nF  [C_0603_1608Metric]
C93  100nF/25V  [C_0603_1608Metric]
C100  100nF VDD  [C_0402_1005Metric]
C101  100nF VDD  [C_0402_1005Metric]
C102  100nF VDD  [C_0402_1005Metric]
C103  100nF VDD  [C_0402_1005Metric]
C104  100nF VDD  [C_0402_1005Metric]
C105  100nF VDD  [C_0402_1005Metric]
C106  100nF VDD  [C_0402_1005Metric]
C107  100nF VDD  [C_0402_1005Metric]
C108  100nF VDD  [C_0402_1005Metric]
C109  100nF VDD  [C_0402_1005Metric]
C110  100nF VDD  [C_0402_1005Metric]
C111  100nF VDD  [C_0402_1005Metric]
C112  100nF VDD  [C_0402_1005Metric]
C113  100nF VDD  [C_0402_1005Metric]
C114  100nF VDD33_USB  [C_0402_1005Metric]
C115  100nF NRST  [C_0402_1005Metric]
C800  4.7uF/100V  [C_1210_3225Metric]
C801  4.7uF/100V  [C_1210_3225Metric]
C802  47nF/100V  [C_0603_1608Metric]
C803  2.2uF/10V  [C_0603_1608Metric]
C804  1uF/25V  [C_0603_1608Metric]
C805  470nF/25V  [C_0603_1608Metric]
C806  47uF/25V  [C_1210_3225Metric]
C807  47uF/25V  [C_1210_3225Metric]
C808  47uF/25V  [C_1210_3225Metric]
C809  47uF/25V  [C_1210_3225Metric]
C_CAN_RAD  100nF  [C_0402_1005Metric]
C_FRAME  100nF  [C_0402_1005Metric]
C_USB_1U  1uF 10V X7R  [C_0603_1608Metric]
C_USB_4U7  4.7uF 10V X7R  [C_0603_1608Metric]
C_USB_100N  100nF 10V X7R  [C_0402_1005Metric]
D1  SMCJ36CA  [D_SMC]
D3  DUAL_UART_ESD  [USON-10_2.5x1.0mm_P0.5mm]
D4  CAN_ESD  [SOT-23]
D8  UART_PPS_ESD  [USON-10_2.5x1.0mm_P0.5mm]
D_USB  TPD4E05U06DQAR  [USON-10_2.5x1.0mm_P0.5mm]
FB1  BLM18BD601SH1  [L_0603_1608Metric]
J1  24V_IN  [Molex_43650-0200_RA_THT_2P]
J6  HOST_UART_2X  [Molex_43045-0600_RA_THT_6P]
J8  EXT_GNSS_PIXHAWK  [JST_GH_SM06B-GHS-TB_1x06-1MP_P1.25mm_Horizontal]
J10  TC2030_SWD  [TagConnect_TC2030_NL]
JUSB1  105017-0001 USB Micro-B  [CONN_105017-0001]
L1  2.2uH  [Coilcraft_XFL4020_4x4]
L8  10uH XAL7070-103MEC  [L_Coilcraft_XAL7070-XXX]
L9  2.2uH  [Coilcraft_XFL4020_4x4]
Q6  CSD19537Q3  [VSON-8_3.3x3.3mm_P0.65mm_NexFET]
Q7  BSS138  [SOT-23]
R1  4.02k 1%  [R_0603_1608Metric]
R2  1.05k 1%  [R_0603_1608Metric]
R5P  100k 1% PG_PU  [R_0603_1608Metric]
R6F  10k 1% FLT_PU  [R_0603_1608Metric]
R7F  10k 1% FLT_PU  [R_0603_1608Metric]
R10  10k 1%  [R_0603_1608Metric]
R40  120R 1%  [R_0603_1608Metric]
R41  10k  [R_0603_1608Metric]
R42  10k  [R_0603_1608Metric]
R61  887k 1%  [R_0603_1608Metric]
R62  29.4k 1%  [R_0603_1608Metric]
R63  34.0k 1%  [R_0603_1608Metric]
R70  0R  [R_0603_1608Metric]
R71  470k 1%  [R_0603_1608Metric]
R72  16.9k 1%  [R_0603_1608Metric]
R73  43.7k 1%  [R_0603_1608Metric]
R90  100k 1% PG_PU  [R_0603_1608Metric]
R600  10k  [R_0603_1608Metric]
R601  33R  [R_0402_1005Metric]
R602  33R  [R_0402_1005Metric]
R603  33R  [R_0402_1005Metric]
R604  33R  [R_0402_1005Metric]
R605  10k  [R_0603_1608Metric]
R800  100k 1%  [R_0603_1608Metric]
R801  9.09k 1%  [R_0603_1608Metric]
R802  100k 1% RT  [R_0603_1608Metric]
R803  100k 1% PG_PU  [R_0603_1608Metric]
R804  499k 1%  [R_0603_1608Metric]
R805  56.0k 1%  [R_0603_1608Metric]
R806  100k 1%  [R_0603_1608Metric]
R_CAN_SHDN  10k 1%  [R_0603_1608Metric]
R_CAN_STB  10k 1%  [R_0603_1608Metric]
R_CAN_TERM  120R 1%  [R_0603_1608Metric]
R_FRAME_PD  47k 1%  [R_0603_1608Metric]
R_USB_CTS  10k 1%  [R_0402_1005Metric]
R_USB_RESET  1k 1%  [R_0402_1005Metric]
R_USB_VBUS_H  22.1k 1%  [R_0402_1005Metric]
R_USB_VBUS_L  47.5k 1%  [R_0402_1005Metric]
R_USB_WAKE  10k 1%  [R_0402_1005Metric]
RAD_C1  GCM188R71C105KA64D  [0603L]
RAD_C2  CGA2B3X7R1H104K050BB  [0402L]
RAD_C3  GCM188R70J225KE22D  [0603L]
RAD_C5  GCM155R71C224KE02D  [0402L]
RAD_C6  GCJ188C70J475KE02J  [FP-GCJ188C70J475KE02J_0603-MFG]
RAD_C8  GCJ188C70J475KE02J  [FP-GCJ188C70J475KE02J_0603-MFG]
RAD_C9  NFM18HC105C1C3D  [FP-NFM18HC105C1C3D_0603-MFG]
RAD_C10  GCM188R71C105KA64D  [0603L]
RAD_C14  GCM155R71A104KA55D  [0402L]
RAD_C15  GCM21BR71A106KE22L  [0805L]
RAD_C17  GCM155R71A104KA55D  [0402L]
RAD_C19  GCM155R71A104KA55D  [0402L]
RAD_C21  GCM155R71C224KE02D  [0402L]
RAD_C22  GCM155R71C224KE02D  [0402L]
RAD_C23  GCM31CR71A226KE02L  [1206_180L]
RAD_C25  GCM31CR71A226KE02L  [1206_180L]
RAD_C26  GCM31CR71A226KE02L  [1206_180L]
RAD_C29  GCM31CR71A226KE02L  [1206_180L]
RAD_C31  GCM21BR71A106KE22L  [0805L]
RAD_C58  NFM18HC105C1C3D  [FP-NFM18HC105C1C3D_0603-MFG]
RAD_C60  GCM188R71C105KA64D  [0603L]
RAD_C81  GCM155R71A104KA55D  [0402L]
RAD_C92  GCM155R71C224KE02D  [0402L]
RAD_C96  GCM155R71C224KE02D  [0402L]
RAD_C99  EEHZC1V680XP  [SM_RADIAL_6.3BMM]
RAD_C100  C3216X7R1H475K160AC  [1206_180L]
RAD_C101  C3216X7R1H475K160AC  [1206_180L]
RAD_C102  GRT155R70J105KE01D  [FP-GRT155R70J105KE01D_0402-MFG]
RAD_C103  GRT155R70J105KE01D  [FP-GRT155R70J105KE01D_0402-MFG]
RAD_C104  CGA3E3X8R1H104K080AB  [0603L]
RAD_C105  GCM155R71C104KA55D  [0402L]
RAD_C106  GCM1555C1H3R9BA16D  [FP-GCM1555C1H3R9BA16D_0402-MFG]
RAD_C107  GCM155R71C224KE02D  [0402L]
RAD_C108  GCM1555C1H3R9BA16D  [FP-GCM1555C1H3R9BA16D_0402-MFG]
RAD_C110  GCM21BR71A106KE22L  [0805L]
RAD_C111  GCM155R71C224KE02D  [0402L]
RAD_C112  GCM21BR71A106KE22L  [0805L]
RAD_C113  GCM155R71C224KE02D  [0402L]
RAD_C114  GCM21BR71A106KE22L  [0805L]
RAD_C115  GCM155R71C224KE02D  [0402L]
RAD_C116  GCM21BR71A106KE22L  [0805L]
RAD_C117  GCM155R71C224KE02D  [0402L]
RAD_C118  CGA4J1X7R1H475K125AC  [FP-CGA4J1X7R1H475K125AC_0805-MFG]
RAD_C119  GCM21BR71A106KE22L  [0805L]
RAD_C123  GCM188R70J225KE22D  [0603L]
RAD_C124  GCJ188C70J475KE02J  [FP-GCJ188C70J475KE02J_0603-MFG]
RAD_C125  CGA4J1X7T0J226M  [0805_155]
RAD_C126  CGA3E3X8R1H104K080AB  [0603L]
RAD_C129  CGA4J1X7T0J226M  [0805_155]
RAD_C130  CGA4J1X7T0J226M  [0805_155]
RAD_C132  CGA4J1X7T0J226M  [0805_155]
RAD_C134  CGA4J1X7T0J226M  [0805_155]
RAD_C137  GCM188R70J225KE22D  [0603L]
RAD_C138  GCM155R71C224KE02D  [0402L]
RAD_C139  GCM155R71C224KE02D  [0402L]
RAD_C140  GCM155R71C224KE02D  [0402L]
RAD_C141  GCM155R71C224KE02D  [0402L]
RAD_C142  GCM155R71C224KE02D  [0402L]
RAD_C143  CGA4J1X7T0J226M  [0805_155]
RAD_C144  GCJ188C70J475KE02J  [FP-GCJ188C70J475KE02J_0603-MFG]
RAD_C145  GCM188R71C105KA64D  [0603L]
RAD_C146  GCM188R70J225KE22D  [0603L]
RAD_C149  GCM188R70J225KE22D  [0603L]
RAD_C150  GCM155R71C104KA55D  [0402L]
RAD_C153  GCJ188C70J475KE02J  [FP-GCJ188C70J475KE02J_0603-MFG]
RAD_C163  GCM155R71C224KE02D  [0402L]
RAD_C164  GCM155R71C224KE02D  [0402L]
RAD_C165  GCM155R71C224KE02D  [0402L]
RAD_C168  GCM155R71C224KE02D  [0402L]
RAD_C170  GCM155R71C224KE02D  [0402L]
RAD_C172  GCM155R71C224KE02D  [0402L]
RAD_C173  CGA4J1X7R1H475K125AC  [FP-CGA4J1X7R1H475K125AC_0805-MFG]
RAD_C174  GCM155R71C224KE02D  [0402L]
RAD_C175  GCM155R71C224KE02D  [0402L]
RAD_C176  GCM155R71C224KE02D  [0402L]
RAD_C177  GCM155R71C224KE02D  [0402L]
RAD_C179  NFM18HC105C1C3D  [FP-NFM18HC105C1C3D_0603-MFG]
RAD_C180  CGA2B3X7R1H473K050BB  [0402L]
RAD_C181  NFM18HC105C1C3D  [FP-NFM18HC105C1C3D_0603-MFG]
RAD_C195  CGA3E3X7R1H224K080AB  [0603L]
RAD_C199  GCM155R71C224KE02D  [0402L]
RAD_C200  GCM155R71C104KA55D  [0402L]
RAD_C201  CGA4J1X7T0J226M  [0805_155]
RAD_C202  CGA4J1X7T0J226M  [0805_155]
RAD_L1  TFM201610ALMA1R5MTAA  [TFM201610ALMA]
RAD_L2  TFM201610ALMAR24MTAA  [FP-TFM201610ALMAR24MTAA_0806 (2016 Metric)-MFG]
RAD_L5  XAL4030-472MEC  [FP-XAL4030-472MEC_SMD2-MFG]
RAD_L6  XEL4030-222MEC  [FP-XEL4030-222MEC_SMT2_4MM0_4MM0-MFG]
RAD_L8  TFM201610ALMAR24MTAA  [FP-TFM201610ALMAR24MTAA_0806 (2016 Metric)-MFG]
RAD_L9  TFM201610ALMAR24MTAA  [FP-TFM201610ALMAR24MTAA_0806 (2016 Metric)-MFG]
RAD_NT1  Net-Tie  [Net-Tie_50milWide_30milLong]  (net tie, no BOM)
RAD_NT2  Net-Tie  [Net-Tie_50milWide_30milLong]  (net tie, no BOM)
RAD_NT3  Net-Tie  [Net-Tie_50milWide_30milLong]  (net tie, no BOM)
RAD_NT4  Net-Tie  [Net-Tie_50milWide_30milLong]  (net tie, no BOM)
RAD_P1  Normally open VPP service pads  [VPP_SERVICE_SMT_D1p5_P2p5]
RAD_R1  ERJ-2GE0R00X  [0402L]
RAD_R2  CRCW04027K50FKED  [0402L]
RAD_R7  CRCW040210K0FKED  [0402L]
RAD_R9  CRCW040210K0FKED  [0402L]
RAD_R13  ERJ-2GE0R00X  [0402L]
RAD_R14  ERJ-2GE0R00X  [0402L]
RAD_R17  ERJ-2GE0R00X  [0402L]
RAD_R26  CRCW040210R2FKED  [0402L]
RAD_R27  ERJ-2GE0R00X  [0402L]
RAD_R29  ERJ-2GE0R00X  [0402L]
RAD_R30  CSNL1206FT1L00  [1206L]
RAD_R32  CRCW040210R2FKED  [0402L]
RAD_R33  ERJ-2GE0R00X  [0402L]
RAD_R35  ERJ-2GE0R00X  [0402L]
RAD_R37  ERJ-2GE0R00X  [0402L]
RAD_R38  CRCW040247K5FKED  [0402L]
RAD_R39  ERJ-1GNF33R2C  [FP-ERJ-1GNF33R2C_0201-MFG]
RAD_R40  ERJ-1GNF33R2C  [FP-ERJ-1GNF33R2C_0201-MFG]
RAD_R41  CRCW040210K0FKED  [0402L]
RAD_R42  ERJ-1GNF33R2C  [FP-ERJ-1GNF33R2C_0201-MFG]
RAD_R43  CRCW040210K0FKED  [0402L]
RAD_R44  ERJ-1GNF33R2C  [FP-ERJ-1GNF33R2C_0201-MFG]
RAD_R45  ERJ-1GNF33R2C  [FP-ERJ-1GNF33R2C_0201-MFG]
RAD_R47  CRCW040210R2FKED  [0402L]
RAD_R49  CRCW040210K0FKED  [0402L]
RAD_R56  CRCW040210R2FKED  [0402L]
RAD_R57  ERJ-2GE0R00X  [0402L]
RAD_R58  ERJ-2GE0R00X  [0402L]
RAD_R59  ERJ-2GE0R00X  [0402L]
RAD_R60  CSNL1206FT1L00  [1206L]
RAD_R62  ERJ-2GE0R00X  [0402L]
RAD_R63  ERJ-2GE0R00X  [0402L]
RAD_R64  CSNL1206FT1L00  [1206L]
RAD_R65  CRCW040210R2FKED  [0402L]
RAD_R66  CRCW040210R2FKED  [0402L]
RAD_R71  ERJ-2GE0R00X  [0402L]
RAD_R73  HCJ0603ZT0R00  [FP-HCJ0603ZT0R00_0603-MFG]
RAD_R75  ERJ-2GE0R00X  [0402L]
RAD_R76  ERJ-2GE0R00X  [0402L]
RAD_R99  CRCW04021K00FKED  [0402L]
RAD_R104  HCJ0603ZT0R00  [FP-HCJ0603ZT0R00_0603-MFG]
RAD_R106  CRCW040210K0FKED  [0402L]
RAD_R111  HCJ0603ZT0R00  [FP-HCJ0603ZT0R00_0603-MFG]
RAD_R116  CRCW04020000Z0EDHP  [0402L]
RAD_R125  CRCW040210K0FKED  [0402L]
RAD_R128  ERJ-2GE0R00X  [0402L]
RAD_R129  ERJ-2GE0R00X  [0402L]
RAD_R186  ERJ-2GE0R00X  [0402L]
RAD_R190  ERJ-2GE0R00X  [0402L]
RAD_R193  CRCW040233R2FKED  [0402L]
RAD_R200  HCJ0603ZT0R00  [FP-HCJ0603ZT0R00_0603-MFG]
RAD_R218  CRCW02010000Z0ED  [0201L]
RAD_R264  CRCW040210K0FKED  [0402L]
RAD_R276  CRCW04022K94FKED  [0402L]
RAD_R277  CRCW04022K94FKED  [0402L]
RAD_R291  ERJ-2GE0R00X  [0402L]
RAD_R292  CRCW04022K20JNED  [0402L]
RAD_R299  CRCW040210K0FKED  [0402L]
RAD_R300  CRCW04027K87FKED  [0402L]
RAD_R301  CRCW040210K0FKED  [0402L]
RAD_R302  CRCW040282K5FKED  [0402L]
RAD_R305  CRCW040210K0FKED  [0402L]
RAD_R307  CRCW040282K5FKED  [0402L]
RAD_R309  CRCW040210K0FKED  [0402L]
RAD_R310  CRCW040210K0FKED  [0402L]
RAD_R311  CRCW04027K87FKED  [0402L]
RAD_R313  CRCW040282K5FKED  [0402L]
RAD_R346  CSNL1206FT1L00  [1206L]
RAD_R348  CRCW040210R2FKED  [0402L]
RAD_R352  CRCW040210R2FKED  [0402L]
RAD_R386  CRCW040233R2FKED  [0402L]
RAD_R409  CRCW040210K0FKED  [0402L]
RAD_TP8  TESTPOINT  [TP_25MIL-SMT]
RAD_U1  GD25B64CWAG  [FP-GD25B64CWAG_WSON8-IPC_C]
RAD_U2  LM63635DQDRRRQ1  [DRR0012E-MFG]
RAD_U8  LP877451A1RXVRQ1  [RXV0028A-MFG]
RAD_U9  INA226AIDGSR  [DGS0010A_L]
RAD_U11  INA226AIDGSR  [DGS0010A_L]
RAD_U12  INA226AIDGSR  [DGS0010A_L]
RAD_U22  INA226AIDGSR  [DGS0010A_L]
RAD_U27  TPS78417QDBVRQ1  [DBV0005A-MFG]
RAD_U29  AWR2944PBGALTRQ1  [ALT0266A-MFG]
RAD_Y3  NX2016SA-50M-STD-CZS-3  [FP-NX2016SA-50M-STD-CZS-3_SMT4_2MM0_1MM6-MFG]
SW1  NRST  [ESwitch_TL3301_GullWing_6x6]
TP1  HOST_UART1_TX  [TestPoint_Pad_D1.0mm]
TP2  HOST_UART1_RX  [TestPoint_Pad_D1.0mm]
TP_RAD_FLASH  Service pad  [TestPoint_Pad_D1.5mm]
TP_RAD_GND  Service pad  [TestPoint_Pad_D1.5mm]
TP_RAD_RESET  Service pad  [TestPoint_Pad_D1.5mm]
TP_RAD_VIO  Service pad  [TestPoint_Pad_D1.5mm]
U1  STM32H753IIT6  [LQFP-176_24x24mm_P0.5mm]
U2  IMU  [ICM-42688-P_LGA14_2.5x3mm_P0.5mm]
U4  CAN_FD  [Texas_DRB0008A]
U5  3V3_BUCK  [VQFN-16-1EP_3x3mm_P0.5mm_EP1.68x1.68mm]
U6  24V_SYS_EFUSE  [Texas_RGE0024C_VQFN-24-1EP_4x4mm_P0.5mm_EP2.1x2.1mm]
U7  RADAR_12V_EFUSE  [TPS259470A_RPW0010A_VQFN-HR-10_2x2mm_P0.475mm]
U8  24V_TO_12V_5A  [Texas_RNP0030B_WQFN-30-1EP_4x6mm_P0.5mm_EP1.8x4.5mm_ThermalVias]
U9  5V_GNSS_BUCK  [VQFN-16-1EP_3x3mm_P0.5mm_EP1.68x1.68mm]
U_CAN_RAD  TCAN3404DRBRQ1  [Texas_DRB0008A]
U_FRAME  SN74LVC1G17DCKR  [DCK0005A_N]
U_USB  CP2102N-A02-GQFN20  [CP2102N_QFN20_3x3_EP_Rev1p5]
Y1  25MHz_OSC  [Oscillator_SMD_ECS_2520MV-xxx-xx-4Pin_2.5x2.0mm]

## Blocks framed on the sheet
RADAR D79 24V / PCB v0.8.0 R9 / 30 TIME GNSS: D8
RADAR D79 24V / PCB v0.8.0 R9 / 20 MCU CORE: J1 Q6 U5-U7 U9
RADAR D79 24V / PCB v0.8.0 R9 / 20 MCU CORE: C3 C4 C6D C6I C7D C90-C93 C800-C802 J10 Y1
RADAR D79 24V / PCB v0.8.0 R9 / 20 MCU CORE: C107 C108 C806-C809 D1 L1 L8 L9 R1 R2 R5P R6F R7F
RADAR D79 24V / PCB v0.8.0 R9 / 40 IMU: R71-R73 R90 R800-R806 U2
RADAR D79 24V / PCB v0.8.0 R9 / Radar interfaces and QSPI: R600-R605
RADAR D79 24V / PCB v0.8.0 R9 / Radar interfaces and QSPI: C40 R40-R42 RAD_U8
RADAR D79 24V / PCB v0.8.0 R9 / Radar interfaces and QSPI: RAD_R37 RAD_R38
RADAR D79 24V / PCB v0.8.0 R9 / Radar service USB and boot: U_USB
RADAR D79 24V / PCB v0.8.0 R9 / Radar service USB and boot: RAD_R300 RAD_R301 U1
RADAR D79 24V / PCB v0.8.0 R9 / Radar service USB and boot: C10-C15 C100-C106 TP_RAD_GND TP_RAD_RESET
RADAR D79 24V / PCB v0.8.0 R9 / Radar 12V to 3V3: C110-C115 FB1 R10 RAD_U2 TP1 TP2
RADAR D79 24V / PCB v0.8.0 R9 / Radar 12V to 3V3: C21 C22 RAD_R9
RADAR D79 24V / PCB v0.8.0 R9 / Radar input and reference: RAD_C60 RAD_C99 RAD_U29
RADAR D79 24V / PCB v0.8.0 R9 / Radar bypass: C_CAN_RAD C_FRAME RAD_C1 RAD_C2 RAD_C106 RAD_C108 RAD_C179 RAD_C181 RAD_U1 RAD_Y3 U_CAN_RAD U_FRAME
RADAR D79 24V / PCB v0.8.0 R9 / Radar bypass: R_CAN_SHDN R_CAN_STB R_CAN_TERM R_FRAME_PD RAD_C117 RAD_C137 RAD_R40-RAD_R45 RAD_R49
RADAR D79 24V / PCB v0.8.0 R9 / Radar bypass: C_USB_1U C_USB_4U7 C_USB_100N D_USB JUSB1 RAD_C105 RAD_C175 RAD_C176 RAD_R128 RAD_R129 RAD_R218 RAD_R264 RAD_R299
RADAR D79 24V / PCB v0.8.0 R9 / Radar PMIC and rail filters: R_USB_CTS R_USB_RESET R_USB_VBUS_H R_USB_VBUS_L R_USB_WAKE RAD_C9 RAD_C58 RAD_R305 RAD_R307 RAD_R309-RAD_R311 RAD_R313 RAD_R386 TP_RAD_FLASH
RADAR D79 24V / PCB v0.8.0 R9 / Radar PMIC and rail filters: RAD_C143 RAD_C144
RADAR D79 24V / PCB v0.8.0 R9 / Radar PMIC and rail filters: RAD_C21-RAD_C23 RAD_C25 RAD_C26 RAD_C29 RAD_C118 RAD_C173 RAD_C195 RAD_L6 RAD_R1 RAD_R2 RAD_R7 RAD_R14 RAD_R17
RADAR D79 24V / PCB v0.8.0 R9 / Radar PMIC and rail filters: RAD_R200 RAD_R291
21_Radar_input_and_reference.SchDoc: RAD_C101 RAD_C104 RAD_C126 RAD_L5 RAD_R276 RAD_R277 RAD_U9
22_Radar_bypass.SchDoc: RAD_C92 RAD_C96 RAD_C102 RAD_C103 RAD_C107 RAD_C110-RAD_C116 RAD_R33 RAD_R35
RADAR D79 24V / PCB v0.8.0 R9 / Radar VPP service: RAD_C139-RAD_C142 RAD_C145 RAD_C146 RAD_C150 RAD_C163-RAD_C165 RAD_C168 RAD_C170 RAD_C172 RAD_C174 RAD_U27
24_Radar_bypass.SchDoc: RAD_C180
25_Radar_PMIC_and_rail_filters.SchDoc: RAD_C6 RAD_C8 RAD_C15 RAD_C31 RAD_C119 RAD_C123-RAD_C125 RAD_C129 RAD_C130 RAD_C132 RAD_C134
26_Radar_PMIC_and_rail_filters.SchDoc: RAD_C199-RAD_C202 RAD_L1 RAD_L2 RAD_L8 RAD_L9 RAD_NT1-RAD_NT4 RAD_R13
27_Radar_PMIC_and_rail_filters.SchDoc: RAD_R71 RAD_R73 RAD_R75 RAD_R76 RAD_R99 RAD_R104 RAD_R106 RAD_R111 RAD_R116 RAD_R125 RAD_R186 RAD_R190 RAD_R193
28_Radar_PMIC_and_rail_filters.SchDoc: RAD_TP8
29_Radar_rail_selection_and_sensing.SchDoc: RAD_C14 RAD_C17 RAD_C19 RAD_C81 RAD_R26 RAD_R27 RAD_R29 RAD_R30 RAD_R32 RAD_U12 RAD_U22
30_Radar_rail_selection_and_sensing.SchDoc: RAD_R56-RAD_R60 RAD_R62 RAD_R64-RAD_R66 RAD_R346 RAD_R348 RAD_R352
31_Radar_VPP_service.SchDoc: RAD_P1 RAD_R409

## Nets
3V3: C2.1 C12.1 C15.1 C20.1 C21.1 C22.1 C40.1 C100.1 C101.1 C102.1 C103.1 C104.1 C105.1 C106.1 C107.1 C108.1 C109.1 C110.1 C111.1 C112.1 C113.1 C114.1 C_FRAME.1 FB1.1 J10.1(Pin_1) L1.2 R5P.2 R6F.2 R7F.2 R70.2 R600.1 R605.1 R803.2 U1.6(VBAT) U1.15(VDD) U1.23(VDD) U1.36(VDD) U1.49(VDD) U1.62(VDD) U1.72(VDD) U1.82(VDD) U1.91(VDD) U1.103(VDD) U1.114(VDD33_USB) U1.127(VDD) U1.136(VDD) U1.149(VDD) U1.159(VDD) U1.171(PDR_ON) U1.172(VDD) U2.5(VDDIO) U2.8(VDD) U4.3(VCC) U5.14(VOS) U_FRAME.5 Y1.4(VDD)
5V_GNSS: C91.1 J8.1(Pin_1) L9.2 R90.2 U9.14(VOS)
BOOT0: R10.1 R70.1 U1.166(BOOT0)
BUCK5_SW: L9.1 U9.1(SW) U9.2(SW) U9.3(SW)
BUCK_SW: L1.1 U5.1(SW) U5.2(SW) U5.3(SW)
CAN_RX: U1.142(PD0) U4.4(RXD)
CAN_TX: U1.143(PD1) U4.1(TXD)
GND: C1.2 C2.2 C3.2 C4.2 C6D.2 C6I.2 C7D.2 C10.2 C11.2 C12.2 C13.2 C14.2 C15.2 C20.2 C21.2 C22.2 C40.2 C90.2 C91.2 C92.2 C93.2 C100.2 C101.2 C102.2 C103.2 C104.2 C105.2 C106.2 C107.2 C108.2 C109.2 C110.2 C111.2 C112.2 C113.2 C114.2 C115.2 C800.2 C801.2 C802.2 C803.2 C804.2 C806.2 C807.2 C808.2 C809.2 C_CAN_RAD.2 C_FRAME.2 C_USB_1U.2 C_USB_4U7.2 C_USB_100N.2 D1.2(A2) D3.3(GND) D3.8(GND) D4.3(GND) D8.3(GND) D8.8(GND) D_USB.3 D_USB.8 J1.2(Pin_2) J6.1(Pin_1) J6.4(Pin_4) J8.6(Pin_6) J10.3(Pin_3) J10.5(Pin_5) JUSB1.5 JUSB1.6 JUSB1.9 JUSB1.10 JUSB1.11 R1.2 R2.2 R10.2 R41.2 R42.2 R63.2 R73.2 R801.2 R802.2 R805.2 R_CAN_SHDN.2 R_CAN_STB.2 R_FRAME_PD.2 R_USB_CTS.1 R_USB_VBUS_L.2 RAD_C1.1 RAD_C2.1 RAD_C5.1 RAD_C6.1 RAD_C8.1 RAD_C9.2 RAD_C10.2 RAD_C15.2 RAD_C22.1 RAD_C23.2 RAD_C25.2 RAD_C26.2 RAD_C29.2 RAD_C31.2 RAD_C58.2 RAD_C60.2 RAD_C92.1 RAD_C96.1 RAD_C99.2(-) RAD_C100.2 RAD_C101.2 RAD_C102.2 RAD_C103.2 RAD_C104.2 RAD_C105.1 RAD_C106.2 RAD_C107.1 RAD_C108.2 RAD_C110.2 RAD_C111.1 RAD_C112.2 RAD_C113.1 RAD_C114.2 RAD_C115.1 RAD_C116.2 RAD_C117.1 RAD_C118.1 RAD_C119.2 RAD_C125.2 RAD_C126.2 RAD_C129.2 RAD_C130.2 RAD_C132.2 RAD_C134.2 RAD_C137.1 RAD_C138.1 RAD_C139.1 RAD_C140.1 RAD_C141.1 RAD_C142.1 RAD_C143.2 RAD_C144.1 RAD_C145.2 RAD_C146.1 RAD_C149.1 RAD_C150.1 RAD_C153.1 RAD_C163.1 RAD_C164.1 RAD_C165.1 RAD_C168.1 RAD_C170.1 RAD_C172.1 RAD_C173.1 RAD_C174.1 RAD_C175.1 RAD_C176.1 RAD_C177.1 RAD_C179.2 RAD_C180.2 RAD_C181.2 RAD_C195.2 RAD_C199.2 RAD_C200.2 RAD_C201.2 RAD_C202.2 RAD_NT1.1 RAD_NT2.2 RAD_NT3.2 RAD_NT4.2 RAD_R1.2 RAD_R2.1 RAD_R292.1 RAD_R302.1 RAD_R307.1 RAD_R313.1 RAD_U1.4(VSS) RAD_U1.9(EP) RAD_U2.9(AGND) RAD_U2.13(PGND/DAP) RAD_U8.12(PGND_B3BST) RAD_U8.26(PGND_B12) RAD_U9.1(A1) RAD_U9.2(A0) RAD_U9.7(GND) RAD_U11.1(A1) RAD_U11.7(GND) RAD_U12.2(A0) RAD_U12.7(GND) RAD_U22.1(A1) RAD_U22.7(GND) RAD_U27.2(GND) RAD_U29.A1(VSSA) RAD_U29.A2(VSSA) RAD_U29.A4(VSSA) RAD_U29.A6(VSSA) RAD_U29.A8(VSSA) RAD_U29.A10(VSSA) RAD_U29.A12(VSS) RAD_U29.A18(VSS) RAD_U29.B2(VSSA) RAD_U29.B4(VSSA) RAD_U29.B6(VSSA) RAD_U29.B8(VSSA) RAD_U29.B10(VSSA) RAD_U29.C1(VSSA) RAD_U29.C2(VSSA) RAD_U29.C3(VSSA) RAD_U29.C4(VSSA) RAD_U29.C5(VSSA) RAD_U29.C6(VSSA) RAD_U29.C7(VSSA) RAD_U29.C8(VSSA) RAD_U29.C9(VSSA) RAD_U29.C10(VSSA) RAD_U29.D2(VSSA) RAD_U29.D3(VSSA) RAD_U29.E1(VSSA) RAD_U29.E2(VSSA) RAD_U29.E3(VSSA) RAD_U29.E11(VSS) RAD_U29.E18(VSS) RAD_U29.F3(VSSA) RAD_U29.F6(VSSA) RAD_U29.F7(VSSA) RAD_U29.F8(VSS) RAD_U29.F9(VSS) RAD_U29.F10(VSS) RAD_U29.F11(VSS) RAD_U29.F12(VSS) RAD_U29.F13(VSS) RAD_U29.G1(VSSA) RAD_U29.G2(VSSA) RAD_U29.G3(VSSA) RAD_U29.G6(VSSA) RAD_U29.G7(VSS) RAD_U29.G8(VSS) RAD_U29.G9(VSS) RAD_U29.G10(VSS) RAD_U29.G11(VSS) RAD_U29.G12(VSS) RAD_U29.G13(VSS) RAD_U29.G14(VSS) RAD_U29.H3(VSSA) RAD_U29.H6(VSSA) RAD_U29.H7(VSS) RAD_U29.H8(VSS) RAD_U29.H9(VSS) RAD_U29.H10(VSS) RAD_U29.H11(VSS) RAD_U29.H12(VSS) RAD_U29.H13(VSS) RAD_U29.J1(VSSA) RAD_U29.J2(VSSA) RAD_U29.J3(VSSA) RAD_U29.J6(VSSA) RAD_U29.J7(VSS) RAD_U29.J8(VSS) RAD_U29.J9(VSS) RAD_U29.J10(VSS) RAD_U29.J11(VSS) RAD_U29.J12(VSS) RAD_U29.J13(VSS) RAD_U29.K3(VSSA) RAD_U29.K6(VSSA) RAD_U29.K7(VSS) RAD_U29.K8(VSS) RAD_U29.K9(VSS) RAD_U29.K10(VSS) RAD_U29.K11(VSS) RAD_U29.K12(VSS) RAD_U29.K13(VSS) RAD_U29.K16(VSS) RAD_U29.L1(VSSA) RAD_U29.L2(VSSA) RAD_U29.L3(VSSA) RAD_U29.L6(VSSA) RAD_U29.L7(VSS) RAD_U29.L8(VSS) RAD_U29.L9(VSS) RAD_U29.L10(VSS) RAD_U29.L11(VSS) RAD_U29.L12(VSS) RAD_U29.L13(VSS) RAD_U29.M3(VSSA) RAD_U29.M6(VSSA) RAD_U29.M7(VSS) RAD_U29.M8(VSS) RAD_U29.M9(VSS) RAD_U29.M10(VSS) RAD_U29.M11(VSS) RAD_U29.M12(VSS) RAD_U29.M13(VSS) RAD_U29.M14(VSS) RAD_U29.N1(VSSA) RAD_U29.N2(VSSA) RAD_U29.N3(VSSA) RAD_U29.N7(VSS) RAD_U29.N8(VSS) RAD_U29.N9(VSS) RAD_U29.N10(VSS) RAD_U29.N11(VSS) RAD_U29.N12(VSS) RAD_U29.N13(VSS) RAD_U29.P8(VSS) RAD_U29.P12(VSS) RAD_U29.P18(VSS) RAD_U29.V1(VSSA) RAD_U29.V2(VSS) RAD_U29.V9(VSS) RAD_U29.V14(VSS) RAD_U29.V18(VSS) RAD_Y3.2(GND) RAD_Y3.4(GND) SW1.2 TP_RAD_GND.1 U1.14(VSS) U1.22(VSS) U1.37(VSSA) U1.48(VSS) U1.61(VSS) U1.71(VSS) U1.90(VSS) U1.102(VSS) U1.113(VSS) U1.126(VSS) U1.135(VSS) U1.148(VSS) U1.158(VSS) U2.6(GND) U2.7(RESV) U2.9(INT2/FSYNC/CLKIN) U4.2(GND) U4.9(THERMAL_PAD) U5.5(FB) U5.6(AGND) U5.15(PGND) U5.16(PGND) U5.17(THERMAL_PAD) U6.8(GND) U6.11(MODE) U6.25(THERMAL_PAD) U7.8(GND) U8.13(AGND) U8.14(AGND) U8.15(AGND) U8.17(SYNC/MODE) U8.19(NC_THERMAL) U8.24(PGND) U8.25(PGND) U8.26(PGND) U8.27(NC_THERMAL) U8.28(NC_THERMAL) U8.29(NC_THERMAL) U8.30(NC_THERMAL) U8.31(THERMAL_PAD) U9.5(FB) U9.6(AGND) U9.15(PGND) U9.16(PGND) U9.17(THERMAL_PAD) U_CAN_RAD.2 U_CAN_RAD.9 U_FRAME.3 U_USB.3(GND) U_USB.12(GND) U_USB.21(EP_GND) Y1.2(GND)
GNSS_PPS: D8.4(D2+) J8.4(Pin_4) U1.40(PA0)
GNSS_RX_EXT: D8.1(D1+) J8.2(Pin_2) U1.96(PD8)
GNSS_TX_EXT: D8.2(D1-) J8.3(Pin_3) U1.97(PD9)
HOST_UART1_RX: R600.2 R602.2 TP2.1 U1.150(PD6)
HOST_UART1_RX_EXT: D3.2(D1-) J6.3(Pin_3) R602.1
HOST_UART1_TX: R601.2 TP1.1 U1.147(PD5)
HOST_UART1_TX_EXT: D3.1(D1+) J6.2(Pin_2) R601.1
HOST_UART2_RX: R604.2 R605.2 U1.121(PA10)
HOST_UART2_RX_EXT: D3.5(D2-) J6.6(Pin_6) R604.1
HOST_UART2_TX: R603.2 U1.120(PA9)
HOST_UART2_TX_EXT: D3.4(D2+) J6.5(Pin_5) R603.1
IMU_DRDY: U1.80(PB11) U2.4(INT1/INT)
IMU_MISO: U1.94(PB14) U2.1(AP_SDO/AP_AD0)
IMU_MOSI: U1.95(PB15) U2.14(AP_SDA/AP_SDIO/AP_SDI)
IMU_NSS: U1.92(PB12) U2.12(AP_CS)
IMU_SCK: U1.93(PB13) U2.13(AP_SCL/AP_SCLK)
MCU_HSE_25M: U1.29(PH0) Y1.3(OUT)
NRST: C115.1 SW1.1 U1.31(NRST)
RAD_CAN_SHDN: R_CAN_SHDN.1 U_CAN_RAD.5
RAD_CAN_STB: R_CAN_STB.1 U_CAN_RAD.8
RAD_FRAME_RAW: R_FRAME_PD.1 RAD_U29.G15(MSS_GPIO_2) U_FRAME.2
RADAR_12V: RAD_C99.1(+) RAD_C101.1 RAD_C118.2 RAD_C173.2 RAD_C195.1 RAD_L5.2 RAD_R7.1 RAD_U2.12(VIN) U7.6(OUT)
RADAR_CANH: D4.1(IO1) R40.1 R_CAN_TERM.1 U4.7(CANH) U_CAN_RAD.7
RADAR_CANL: D4.2(IO2) R40.2 R_CAN_TERM.2 U4.6(CANL) U_CAN_RAD.6
RADAR_EFUSE_FLT: R7F.1 U1.2(PE3) U7.4(FLT)
RADAR_REF: U1.79(PB10) U_FRAME.4
SHDN_PD: R42.1 U4.5(SHDN)
STB_PD: R41.1 U4.8(STB)
SWCLK: J10.4(Pin_4) U1.137(PA14)
SWDIO: J10.2(Pin_2) U1.124(PA13)
SWO: J10.6(Pin_6) U1.161(PB3)
SYS_EFUSE_FLT: R6F.1 U1.1(PE2) U6.14(FLT)
TI_1V0: RAD_C114.1 RAD_C115.2 RAD_C116.1 RAD_C117.2 RAD_C179.1 RAD_C179.3 RAD_C181.1 RAD_C181.3 RAD_R56.1 RAD_R64.2 RAD_U22.8(VBUS) RAD_U29.D6(VDDA_10RF2) RAD_U29.D7(VDDA_10RF2) RAD_U29.M4(VDDA_10RF1)
TI_1V0_FILTERED: RAD_R64.1 RAD_R66.1 RAD_R73.2 RAD_R111.2
TI_1V2: RAD_C92.2 RAD_C96.2 RAD_C137.2 RAD_C138.2 RAD_C139.2 RAD_C140.2 RAD_C141.2 RAD_C142.2 RAD_C146.2 RAD_R26.1 RAD_R30.2 RAD_U9.8(VBUS) RAD_U29.E12(VDD) RAD_U29.E13(VDD) RAD_U29.E14(VDD) RAD_U29.F14(VDD) RAD_U29.H14(VDD) RAD_U29.J14(VDD) RAD_U29.K14(VDD) RAD_U29.L14(VDD) RAD_U29.N6(VDD) RAD_U29.N14(VDD) RAD_U29.P6(VDD) RAD_U29.P7(VDD) RAD_U29.P9(VDD) RAD_U29.P10(VDD) RAD_U29.P11(VDD) RAD_U29.P13(VDD) RAD_U29.P14(VDD) RAD_U29.V7(VDD_SRAM) RAD_U29.V13(VNWA)
TI_1V4_APLL: RAD_C103.1 RAD_U29.H4(VOUT_14APLL)
TI_1V4_SYNTH: RAD_C102.1 RAD_U29.G4(VOUT_14SYNTH)
TI_1V8: RAD_C5.2 RAD_C107.2 RAD_C110.1 RAD_C111.2 RAD_C112.1 RAD_C113.2 RAD_C163.2 RAD_C164.2 RAD_C165.2 RAD_C168.2 RAD_C170.2 RAD_C172.2 RAD_R47.1 RAD_R60.2 RAD_U11.8(VBUS) RAD_U29.D9(VDDA_18CLK) RAD_U29.D18(VIOIN_18) RAD_U29.E4(VDDA_18VCO) RAD_U29.K17(VIOIN_18LVDS) RAD_U29.K18(VIOIN_18CSI) RAD_U29.P1(VDDA_18BB) RAD_U29.R1(VDDA_18PM) RAD_U29.U18(VIOIN_18) RAD_U29.V10(VIOIN_18)
TI_1V8_FILTERED: RAD_R60.1 RAD_R65.1 RAD_R104.2
TI_3V3: RAD_C174.2 RAD_C175.2 RAD_C176.2 RAD_C177.2 RAD_R346.2 RAD_R348.1 RAD_U12.8(VBUS) RAD_U29.A13(VIOIN) RAD_U29.B18(VIOIN) RAD_U29.R18(VIOIN) RAD_U29.V8(VIOIN) RAD_U29.V15(VIOIN)
TI_3V3_VIO: C_CAN_RAD.1 C_USB_1U.1 C_USB_4U7.1 C_USB_100N.1 R_USB_RESET.1 R_USB_WAKE.1 RAD_R37.1 RAD_R38.2 RAD_R41.2 RAD_R43.2 RAD_R49.2 RAD_R106.2 RAD_R116.2 RAD_R264.2 RAD_R276.2 RAD_R277.2 RAD_R301.2 RAD_R309.2 RAD_R311.2 RAD_R346.1 RAD_R352.1 RAD_R409.2 TP_RAD_VIO.1 U_CAN_RAD.3 U_USB.6(VDD) U_USB.7(VREGIN)
TI_3V3REG_ENA: RAD_R7.2 RAD_U2.10(EN)
TI_3V3REG_MODE: RAD_R9.1 RAD_U2.6(SYNC/MODE)
TI_3V3REG_VCC: RAD_C10.1 RAD_R9.2 RAD_U2.3(VCC)
TI_5V0: RAD_C119.1 RAD_U8.10(VOUT_BST)
TI_+3.3VD: RAD_C124.2 RAD_R116.1 RAD_U8.9(VIO_LDO)
TI_AGND: RAD_C3.1 RAD_C123.1 RAD_C124.1 RAD_NT1.2 RAD_NT2.1 RAD_NT3.1 RAD_NT4.1 RAD_U8.5(AGND) RAD_U8.5-19 RAD_U8.19(AGND)
TI_AR_NERROUT: RAD_R76.1 RAD_U29.C11(~{ERROR_OUT})
TI_AR_NRST: RAD_C105.2 RAD_R99.1 RAD_R264.1 RAD_U29.H16(~{RESET}) TP_RAD_RESET.1
TI_AR_WRMRST: RAD_U29.B12(WARM_RESET)
TI_BSS_UARTA_TX: RAD_U29.M16(BSS_UARTA_TX)
TI_CANA_NSTB: RAD_R13.1
TI_CANB_NSTB: RAD_R17.1
TI_CSI2_RX0_0_N: RAD_U29.N18(CSI2_RX0M0)
TI_CSI2_RX0_0_P: RAD_U29.N17(CSI2_RX0P0)
TI_CSI2_RX0_1_N: RAD_U29.M18(CSI2_RX0M1)
TI_CSI2_RX0_1_P: RAD_U29.M17(CSI2_RX0P1)
TI_CSI2_RX0_CLK_N: RAD_U29.L18(CSI2_RX0CLKM)
TI_CSI2_RX0_CLK_P: RAD_U29.L17(CSI2_RX0CLKP)
TI_DSS_UARTA_RX: RAD_U29.B14(DSS_UARTA_RX)
TI_DSS_UARTA_TX: RAD_U29.A15(DSS_UARTA_TX)
TI_FB_B1: RAD_R14.1 RAD_U8.3(FB_B1)
TI_FB_B2: RAD_R71.1 RAD_U8.21(FB_B2)
TI_FB_B3: RAD_R291.1 RAD_U8.17(FB_B3)
TI_GPADC1: RAD_U29.P3(ADC1)
TI_GPADC2: RAD_U29.P2(ADC2)
TI_GPADC3: RAD_U29.R3(ADC3)
TI_GPADC4: RAD_U29.R2(ADC4)
TI_GPADC5: RAD_U29.T3(ADC5)
TI_GPADC6: RAD_U29.U2(ADC6)
TI_GPADC7: RAD_U29.T1(ADC7)
TI_GPADC8: RAD_U29.T2(ADC8)
TI_GPADC9: RAD_U29.U1(ADC9)
TI_GPIO_3: RAD_U29.P16(MSS_GPIO_3)
TI_GPIO_4: RAD_U29.L15(MSS_GPIO_4)
TI_GPIO_8: RAD_U29.T18(MSS_GPIO_8)
TI_GPIO_9: RAD_U29.N15(MSS_GPIO_9)
TI_GPIO_30: RAD_U29.P17(MSS_GPIO_30)
TI_GPIO_31: RAD_U29.U17(MSS_GPIO_31)
TI_LVDS_TX0_N: RAD_U29.F18(LVDS_TXM0)
TI_LVDS_TX0_P: RAD_U29.F17(LVDS_TXP0)
TI_LVDS_TX1_N: RAD_U29.J18(LVDS_TXM1)
TI_LVDS_TX1_P: RAD_U29.J17(LVDS_TXP1)
TI_LVDS_TX2_CLK_N: RAD_U29.G18(LVDS_TXM2_CLKM)
TI_LVDS_TX2_CLK_P: RAD_U29.G17(LVDS_TXP2_CLKP)
TI_LVDS_TX3_FRCLK_N: RAD_U29.H18(LVDS_TXM3_FRCLKM)
TI_LVDS_TX3_FRCLK_P: RAD_U29.H17(LVDS_TXP3_FRCLKP)
TI_MCU_CLK_OUT: RAD_U29.R15(MCU_CLKOUT)
TI_MSS_EPWMA0: RAD_U29.E15(MSS_EPWMA0)
TI_MSS_EPWMA1: RAD_U29.C18(MSS_EPWMA1)
TI_MSS_EPWMB0: RAD_U29.C17(MSS_EPWMB0)
TI_MSS_GPIO_0: RAD_U29.B15(MSS_GPIO_0)
TI_MSS_GPIO_1: RAD_U29.A16(MSS_GPIO_1)
TI_MSS_GPIO_11: RAD_U29.J15(MSS_GPIO_11)
TI_MSS_GPIO_28: RAD_U29.R17(MSS_GPIO_28)
TI_MSS_I2CA_SCL: RAD_R27.2 RAD_R33.2 RAD_R57.2 RAD_R58.2 RAD_R276.1
TI_MSS_I2CA_SDA: RAD_R29.2 RAD_R35.2 RAD_R59.2 RAD_R62.2 RAD_R277.1
TI_MSS_MCANA_RX: RAD_U29.D16(MSS_MCANA_RX) U_CAN_RAD.4
TI_MSS_MCANA_TX: RAD_U29.D17(MSS_MCANA_TX) U_CAN_RAD.1
TI_MSS_MCANB_RX: RAD_U29.A17(MSS_MCANB_RX)
TI_MSS_MCANB_TX: RAD_U29.B17(MSS_MCANB_TX)
TI_MSS_MDIO_CLK: RAD_U29.R4(MSS_MDIO_CLK)
TI_MSS_MDIO_DATA: RAD_U29.T5(MSS_MDIO_DATA)
TI_MSS_RGMII_RCLK: RAD_U29.T9(MSS_RGMII_RCLK)
TI_MSS_RGMII_RCTL: RAD_U29.T7(MSS_RGMII_RCTL)
TI_MSS_RGMII_RD0: RAD_U29.V6(MSS_RGMII_RD0)
TI_MSS_RGMII_RD1: RAD_U29.V4(MSS_RGMII_RD1)
TI_MSS_RGMII_RD2: RAD_U29.V5(MSS_RGMII_RD2)
TI_MSS_RGMII_RD3: RAD_U29.U10(MSS_RGMII_RD3)
TI_MSS_RGMII_TCLK: RAD_U29.V3(MSS_RGMII_TCLK)
TI_MSS_RGMII_TCTL: RAD_U29.R6(MSS_RGMII_TCTL)
TI_MSS_RGMII_TD0: RAD_U29.U7(MSS_RGMII_TD0)
TI_MSS_RGMII_TD1: RAD_U29.U5(MSS_RGMII_TD1)
TI_MSS_RGMII_TD2: RAD_U29.U6(MSS_RGMII_TD2)
TI_MSS_RGMII_TD3: RAD_U29.U4(MSS_RGMII_TD3)
TI_MSS_RS232RX: RAD_U29.F16(MSS_RS232_RX)
TI_MSS_RS232TX: RAD_U29.E17(MSS_RS232_TX)
TI_MSS_SPIA_CLK: RAD_U29.T16(MSS_MIBSPIA_CLK)
TI_MSS_SPIA_CS0: RAD_U29.T15(MSS_MIBSPIA_CS0)
TI_MSS_SPIA_HOSTIRQ: RAD_U29.V17(MSS_MIBSPIA_HOSTIRQ)
TI_MSS_SPIA_MOSI: RAD_U29.U15(MSS_MIBSPIA_MOSI)
TI_MSS_SPIB_CS0: RAD_U29.U14(MSS_MIBSPIB_CS0)
TI_MSS_SPIB_CS1: RAD_U29.V16(MSS_MIBSPIB_CS1)
TI_MSS_SPIB_MISO: RAD_U29.U13(MSS_MIBSPIB_MISO)
TI_MSS_UARTA_RX: RAD_R129.1 RAD_U29.B16(MSS_UARTA_RX)
TI_NERR_MCU: RAD_R76.2 RAD_U8.16(~{ERR}/GPO2)
TI_NetC1_2: RAD_C1.2 RAD_C2.2 RAD_R37.2 RAD_U1.8(VCC)
TI_NetC14_1: RAD_C14.1 RAD_R26.2 RAD_U9.9(VIN-)
TI_NetC14_2: RAD_C14.2 RAD_R32.2 RAD_U9.10(VIN+)
TI_NetC17_1: RAD_C17.1 RAD_R47.2 RAD_U11.9(VIN-)
TI_NetC17_2: RAD_C17.2 RAD_R65.2 RAD_U11.10(VIN+)
TI_NetC19_1: RAD_C19.1 RAD_R348.2 RAD_U12.9(VIN-)
TI_NetC19_2: RAD_C19.2 RAD_R352.2 RAD_U12.10(VIN+)
TI_NetC21_1: RAD_C21.1 RAD_U2.2(BOOT)
TI_NetC21_2: RAD_C21.2 RAD_L6.1 RAD_U2.1(SW)
TI_NetC81_1: RAD_C81.1 RAD_R56.2 RAD_U22.9(VIN-)
TI_NetC81_2: RAD_C81.2 RAD_R66.2 RAD_U22.10(VIN+)
TI_NetC100_1: RAD_C100.1 RAD_L5.1
TI_NetC104_1: RAD_C104.1 RAD_C126.1
TI_NetC123_2: RAD_C123.2 RAD_U8.18(VOUT_VLDO)
TI_NetC149_2: RAD_C149.2 RAD_P1.2 RAD_U27.5(OUT)
TI_NetJ17_1: RAD_R300.2 TP_RAD_FLASH.1
TI_NetL1_1: RAD_L1.1 RAD_U8.11(SW_BST)
TI_NetR1_1: RAD_R1.1 RAD_U2.5(VSEL)
TI_NetR2_2: RAD_R2.2 RAD_U2.4(RT)
TI_NetR3_2: RAD_U29.U9(MSS_I2CA_SCL)
TI_NetR4_2: RAD_U2.7(~{RESET})
TI_NetR27_1: RAD_R27.1 RAD_U9.5(SCL)
TI_NetR29_1: RAD_R29.1 RAD_U9.4(SDA)
TI_NetR31_2: RAD_U29.R8(MSS_I2CA_SDA)
TI_NetR33_1: RAD_R33.1 RAD_U11.5(SCL)
TI_NetR35_1: RAD_R35.1 RAD_U11.4(SDA)
TI_NetR57_1: RAD_R57.1 RAD_U22.5(SCL)
TI_NetR58_1: RAD_R58.1 RAD_U12.5(SCL)
TI_NetR59_1: RAD_R59.1 RAD_U12.4(SDA)
TI_NetR62_1: RAD_R62.1 RAD_U22.2(A0) RAD_U22.4(SDA)
TI_NetR63_1: RAD_R63.1 RAD_U8.1(SCK_SPI)
TI_NetR159_2: RAD_R409.1 RAD_U27.3(EN)
TI_NetR186_1: RAD_R186.1 RAD_U8.8(SDI_SPI)
TI_NetR190_2: RAD_R190.2 RAD_R292.2 RAD_U8.4(CS_SPI/WD_DIS)
TI_NetR193_1: RAD_R193.1 RAD_U8.2(SDO_SPI)
TI_NetR298_1: RAD_R299.2 RAD_R300.1 RAD_R302.2
TI_NetR304_1: RAD_R305.2 RAD_R307.2
TI_NetR308_1: RAD_R310.2 RAD_R311.1 RAD_R313.2
TI_NetR380_2: RAD_U29.T13(MSS_MIBSPIB_CLK)
TI_NetR381_2: RAD_U29.V12(MSS_MIBSPIB_MOSI)
TI_NetR386_2: RAD_R386.2 RAD_U29.D15(TDO)
TI_NetR392_2: RAD_U29.U16(MSS_MIBSPIA_MISO)
TI_NetTP8_1: RAD_TP8.1 RAD_U8.22(VMON1/GPO1)
TI_NRSTOUT: RAD_R99.2 RAD_U8.6(~{RSTOUT})
TI_OSC_CLK_OUT_ETHERNET: RAD_U29.B11(OSC_CLK_OUT_ETH)
TI_OSC_CLKTOP: RAD_U29.A11(OSC_CLKOUT)
TI_PMIC_CLK: RAD_R75.1
TI_PMIC_CLK_OUT: RAD_R218.1 RAD_U29.T17(PMIC_CLKOUT)
TI_PMIC_EN: RAD_R125.1 RAD_U8.15(ENABLE)
TI_PMIC_NINT: RAD_R13.2 RAD_R17.2 RAD_R106.1 RAD_U8.7(~{INT})
TI_PMIC_SPI_CLK: RAD_R63.2
TI_PMIC_SPI_CS0: RAD_R190.1
TI_PMIC_SPI_MISO: RAD_R193.2
TI_PMIC_SPI_MOSI: RAD_R186.2
TI_PMICOUT_1V0: RAD_C132.1 RAD_C134.1 RAD_L8.2 RAD_R71.2 RAD_R73.1 RAD_R111.1
TI_PMICOUT_1V2: RAD_C129.1 RAD_C130.1 RAD_L2.2 RAD_R30.1 RAD_R32.1 RAD_R291.2
TI_PMICOUT_1V8: RAD_C60.1 RAD_C125.1 RAD_L9.2 RAD_R14.2 RAD_R104.1
TI_PVIN3V3: RAD_C3.2 RAD_C6.2 RAD_C8.2 RAD_C9.1 RAD_C9.3 RAD_C15.1 RAD_C31.1 RAD_C58.1 RAD_C58.3 RAD_C143.1 RAD_C144.2 RAD_C153.2 RAD_C199.1 RAD_C200.1 RAD_C201.1 RAD_C202.1 RAD_L1.2 RAD_R125.2 RAD_R200.2 RAD_U8.13(PVIN_B3) RAD_U8.20(VCCA) RAD_U8.25(PVIN_B2) RAD_U8.27(PVIN_B1)
TI_QSPI_CS: RAD_R38.1 RAD_U1.1(~{CS}) RAD_U29.U12(MSS_QSPI_CS)
TI_QSPI_D0: RAD_R45.2 RAD_U29.U11(MSS_QSPI_0)
TI_QSPI_D0_FLASH: RAD_R45.1 RAD_U1.5(SI(IO2))
TI_QSPI_D1: RAD_R39.1 RAD_R49.1 RAD_U29.V11(MSS_QSPI_1)
TI_QSPI_D1_FLASH: RAD_R39.2 RAD_U1.2(SO(IO1))
TI_QSPI_D2: RAD_R42.1 RAD_R43.1 RAD_U29.T11(MSS_QSPI_2)
TI_QSPI_D2_FLASH: RAD_R42.2 RAD_U1.3(IO2)
TI_QSPI_D3: RAD_R40.2 RAD_R41.1 RAD_U29.R12(MSS_QSPI_3)
TI_QSPI_D3_FLASH: RAD_R40.1 RAD_U1.7(IO3)
TI_QSPI_SCLK: RAD_R44.2 RAD_U29.R10(MSS_QSPI_CLK)
TI_QSPI_SCLK_FLASH: RAD_R44.1 RAD_U1.6(SCLK)
TI_REGOUT_3V3: RAD_C22.2 RAD_C23.1 RAD_C25.1 RAD_C26.1 RAD_C29.1 RAD_C145.1 RAD_L6.2 RAD_R200.1 RAD_U2.8(FB) RAD_U9.6(VS+) RAD_U11.2(A0) RAD_U11.6(VS+) RAD_U12.1(A1) RAD_U12.6(VS+) RAD_U22.6(VS+) RAD_U27.1(IN)
TI_RX1: RAD_U29.M2(RX1)
TI_RX2: RAD_U29.K2(RX2)
TI_RX3: RAD_U29.H2(RX3)
TI_RX4: RAD_U29.F2(RX4)
TI_SOP0_TDO: RAD_R310.1 RAD_R386.1
TI_SOP1_MSS_SPIB_CS2: RAD_R305.1 RAD_U29.R14(MSS_MIBSPIB_CS2)
TI_SOP2_PMIC_CLK: RAD_R218.2 RAD_R299.1
TI_SOP3_MSS_UARTB_TX: RAD_R301.1 RAD_U29.A14(MSS_UARTB_TX)
TI_SOP4_MSS_UARTA_TX: RAD_R128.1 RAD_R309.1 RAD_U29.C16(MSS_UARTA_TX)
TI_SW_B1: RAD_L9.1 RAD_U8.28(SW_B1)
TI_SW_B2: RAD_L8.1 RAD_U8.24(SW_B2)
TI_SW_B3: RAD_L2.1 RAD_U8.14(SW_B3)
TI_SYNCCLKIN: RAD_R75.2 RAD_U8.23(SYNCCLKIN)
TI_TCK: RAD_U29.C12(TCK)
TI_TDI: RAD_U29.D13(TDI)
TI_TMS: RAD_U29.C14(TMS)
TI_TX1: RAD_U29.B3(TX1)
TI_TX2: RAD_U29.B5(TX2)
TI_TX3: RAD_U29.B7(TX3)
TI_TX4: RAD_U29.B9(TX4)
TI_VBGAP: RAD_C180.1 RAD_U29.K4(VBGAP)
TI_VPP_1P7: RAD_C150.2 RAD_P1.1 RAD_U29.U3(VPP)
TI_VPP_EN: RAD_U29.U8(MSS_GPIO_17)
TI_XDSET_UARTA_RX: RAD_R129.2 U_USB.18(TXD)
TI_XDSET_UARTA_TX: RAD_R128.2 U_USB.17(RXD)
TI_XREF_CLK0: RAD_U29.B13(XREF_CLK0)
TI_XREF_CLK1: RAD_U29.D11(XREF_CLK1)
TI_XTALM: RAD_C108.1 RAD_U29.B1(CLKM) RAD_Y3.3(2_XTAL)
TI_XTALP: RAD_C106.1 RAD_U29.D1(CLKP) RAD_Y3.1(1_XTAL)
U5_PG: R5P.1 U5.4(PG)
U5_SS_LOCAL: C3.1 U5.9(SS/TR)
U6_BGATE: Q6.4(G) Q7.3(D) U6.3(B_GATE)
U6_DRV: Q7.1(G) U6.4(DRV)
U6_DVDT: C6D.1 U6.9(dVdT)
U6_ILIM_LOCAL: R1.1 U6.10(ILIM)
U6_IN_BLOCKED: Q6.5(D) U6.1(IN) U6.2(IN)
U6_OVP_LOCAL: R62.2 R63.1 U6.7(OVP)
U6_PGTH_LOCAL: R804.2 R805.1 U6.15(PGTH)
U6_UVLO_LOCAL: R61.2 R62.1 U6.6(UVLO)
U7_DVDT: C7D.1 U7.7(DVDT)
U7_ILIM_LOCAL: R2.1 U7.9(ILM)
U7_OVLO_LOCAL: R72.2 R73.1 U7.2(OVLO)
U7_UVLO_LOCAL: R71.2 R72.1 U7.1(EN/UVLO)
U8_BOOT: C805.1 U8.6(BOOT)
U8_ENABLE: R806.1 U6.16(PGOOD) U8.18(EN)
U8_FB_LOCAL: R800.2 R801.1 U8.12(FB)
U8_PGOOD: R803.1 U8.16(PGOOD)
U8_RT_LOCAL: R802.1 U8.10(RT)
U8_SW: C805.2 L8.1 U8.1(SW) U8.2(SW) U8.3(SW) U8.4(SW) U8.5(SW)
U8_VCC: C803.1 U8.8(VCC)
U9_PG: R90.1 U9.4(PG)
U9_SS_LOCAL: C92.1 U9.9(SS/TR)
USB_BRIDGE_RESET_N: R_USB_RESET.2 U_USB.9(RESET_N)
USB_CTS_N: R_USB_CTS.2 U_USB.15(CTS)
USB_DM: D_USB.2 JUSB1.2 U_USB.5(D-)
USB_DP: D_USB.1 JUSB1.3 U_USB.4(D+)
USB_VBUS: D_USB.4 JUSB1.1 R_USB_VBUS_H.1
USB_VBUS_SENSE: R_USB_VBUS_H.2 R_USB_VBUS_L.1 U_USB.8(VBUS_SENSE)
USB_WAKE_N: R_USB_WAKE.2 U_USB.13(WAKEUP)
V12_SYS: C1.1 C4.1 C90.1 C93.1 C804.1 C806.1 C807.1 C808.1 C809.1 L8.2 R71.1 R800.1 U5.10(AVIN) U5.11(PVIN) U5.12(PVIN) U5.13(EN) U7.5(IN) U8.9(BIAS) U9.10(AVIN) U9.11(PVIN) U9.12(PVIN) U9.13(EN)
VCAP1_LOCAL: C10.1 U1.81(VCAP)
VCAP2_LOCAL: C11.1 U1.125(VCAP)
VDDA_FILTERED: C13.1 C14.1 FB1.2 U1.38(VREF+) U1.39(VDDA)
VIN_PROTECTED_24V: C800.1 C801.1 C802.1 R804.1 R806.2 U6.17(OUT) U6.18(OUT) U8.20(PVIN) U8.21(PVIN) U8.22(PVIN)
VIN_RAW: C6I.1 D1.1(A1) J1.1(Pin_1) Q6.1(S) Q6.2(S) Q6.3(S) Q7.2(S) R61.1 U6.5(IN_SYS)

Not connected (* = marked no-connect by the designer): D3 6(NC) 7(NC) 9(NC) 10(NC); D8 5(D2-) 6(NC) 7(NC) 9(NC) 10(NC); D_USB 5 6 7 9 10; J1 Un1; J6 Un1; J8 5(Pin_5) MP; J10 Un1 Un2 Un3; JUSB1 4 7 8; RAD_U2 11(NC); RAD_U9 3(ALERT); RAD_U11 3(ALERT); RAD_U12 3(ALERT); RAD_U22 3(ALERT); RAD_U27 4(NC); U1 3(PE4) 4(PE5) 5(PE6) 7(PI8) 8(PC13) 9(PC14) 10(PC15) 11(PI9) 12(PI10) 13(PI11) 16(PF0) 17(PF1) 18(PF2) 19(PF3) 20(PF4) 21(PF5) 24(PF6) 25(PF7) 26(PF8) 27(PF9) 28(PF10) 30(PH1) 32(PC0) 33(PC1) 34(PC2_C) 35(PC3_C) 41(PA1) 42(PA2) 43(PH2) 44(PH3) 45(PH4) 46(PH5) 47(PA3) 50(PA4) 51(PA5) 52(PA6) 53(PA7) 54(PC4) 55(PC5) 56(PB0) 57(PB1) 58(PB2) 59(PF11) 60(PF12) 63(PF13) 64(PF14) 65(PF15) 66(PG0) 67(PG1) 68(PE7) 69(PE8) 70(PE9) 73(PE10) 74(PE11) 75(PE12) 76(PE13) 77(PE14) 78(PE15) 83(PH6) 84(PH7) 85(PH8) 86(PH9) 87(PH10) 88(PH11) 89(PH12) 98(PD10) 99(PD11) 100(PD12) 101(PD13) 104(PD14) 105(PD15) 106(PG2) 107(PG3) 108(PG4) 109(PG5) 110(PG6) 111(PG7) 112(PG8) 115(PC6) 116(PC7) 117(PC8) 118(PC9) 119(PA8) 122(PA11) 123(PA12) 128(PH13) 129(PH14) 130(PH15) 131(PI0) 132(PI1) 133(PI2) 134(PI3) 138(PA15) 139(PC10) 140(PC11) 141(PC12) 144(PD2) 145(PD3) 146(PD4) 151(PD7) 152(PG9) 153(PG10) 154(PG11) 155(PG12) 156(PG13) 157(PG14) 160(PG15) 162(PB4) 163(PB5) 164(PB6) 165(PB7) 167(PB8) 168(PB9) 169(PE0) 170(PE1) 173(PI4) 174(PI5) 175(PI6) 176(PI7); U2 2(RESV) 3(RESV) 10(RESV) 11(RESV); U5 7(FSW) 8(DEF); U6 12(SHDN) 13(IMON) 19(NC) 20(NC) 21(NC) 22(NC) 23(NC) 24(NC); U7 3(AUXOFF) 10(ITIMER); U8 7(NC) 11(SS/TRK) 23(NC); U9 7(FSW) 8(DEF); U_FRAME 1; U_USB 1(GPIO1) 2(GPIO0) 10(NC) 11(SUSPEND_N) 14(SUSPEND) 16(RTS) 19(GPIO3) 20(GPIO2); Y1 1(TRI_STATE)

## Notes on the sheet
- RADAR D79 24V / PCB v0.8.0 R9 / 10 POWER INPUT
- Engineering schematic / sheet 1/31 / release 2.2.4-RC6
- Engineering schematic / sheet 2/31 / release 2.2.4-RC6
- Engineering schematic / sheet 3/31 / release 2.2.4-RC6
- Engineering schematic / sheet 4/31 / release 2.2.4-RC6
- RADAR D79 24V / PCB v0.8.0 R9 / 60 HOST UART
- Engineering schematic / sheet 5/31 / release 2.2.4-RC6
- RADAR D79 24V / PCB v0.8.0 R9 / 50 RADAR IO CAN
- Engineering schematic / sheet 6/31 / release 2.2.4-RC6
- RADAR D79 24V / PCB v0.8.0 R9 / 70 DEBUG BOOT
- Engineering schematic / sheet 7/31 / release 2.2.4-RC6
- RADAR D79 24 V / FULL ELEMENT SCHEMATIC / PCB v0.8.0 R9
- All 31 native schematic sheets flattened at 1:1 scale. Complete inter-sheet electrical connectivity is shown below the sheet field.
- Civil drone tracking system. Measurement and target-state output only. Production authority: NOT_AUTHORIZED.
- 01_10_POWER_INPUT.SchDoc
- 02_10_POWER_INPUT.SchDoc
- 03_10_POWER_INPUT.SchDoc
- 04_10_POWER_INPUT.SchDoc
- 05_60_HOST_UART.SchDoc
- 06_50_RADAR_IO_CAN.SchDoc
- 07_70_DEBUG_BOOT.SchDoc
- RF TRACT AND PRINTED ANTENNA ARRAYS
- 76 to 81 GHz / 4 TX + 4 coherent RX / eight patches per channel
- TX1  TI_TX1 / B3
- Engineering schematic / sheet 13/31 / release 2.2.4-RC6
- RAD_U29
- AWR2944P
- TX2  TI_TX2 / B5
- FMCW RF front end
- TX3  TI_TX3 / B7
- coherent TX/RX
- TX4  TI_TX4 / B9
- phase angle inputs
- RX1  TI_RX1 / M2
- RX2  TI_RX2 / K2
- RX3  TI_RX3 / H2
- (near Q6) Engineering schematic / sheet 9/31 / release 2.2.4-RC6
- Engineering schematic / sheet 8/31 / release 2.2.4-RC6
- (near C802) Engineering schematic / sheet 10/31 / release 2.2.4-RC6
- (near R6F) Engineering schematic / sheet 11/31 / release 2.2.4-RC6
- Engineering schematic / sheet 12/31 / release 2.2.4-RC6
- Engineering schematic / sheet 14/31 / release 2.2.4-RC6
- Engineering schematic / sheet 15/31 / release 2.2.4-RC6
- (near D8) RX4  TI_RX4 / F2
- (near D8) Controlled-impedance feeds and matching geometry are implemented in PCB copper.
- 08_30_TIME_GNSS.SchDoc
- 09_20_MCU_CORE.SchDoc
- 10_20_MCU_CORE.SchDoc
- 11_20_MCU_CORE.SchDoc
- 12_40_IMU.SchDoc
- 13_Radar_interfaces_and_QSPI.SchDoc
- 14_Radar_interfaces_and_QSPI.SchDoc
- 15_Radar_interfaces_and_QSPI.SchDoc
- Engineering schematic / sheet 16/31 / release 2.2.4-RC6
- (near U1) Engineering schematic / sheet 17/31 / release 2.2.4-RC6
- (near C105) Engineering schematic / sheet 18/31 / release 2.2.4-RC6
- Engineering schematic / sheet 19/31 / release 2.2.4-RC6
- Engineering schematic / sheet 20/31 / release 2.2.4-RC6
- (near RAD_U29) Engineering schematic / sheet 21/31 / release 2.2.4-RC6
- Engineering schematic / sheet 22/31 / release 2.2.4-RC6
- Engineering schematic / sheet 23/31 / release 2.2.4-RC6
- 16_Radar_service_USB_and_boot.SchDoc
- 17_Radar_service_USB_and_boot.SchDoc
- 18_Radar_service_USB_and_boot.SchDoc
- 19_Radar_12V_to_3V3.SchDoc
- 20_Radar_12V_to_3V3.SchDoc
- 23_Radar_bypass.SchDoc
- RADAR D79 24V / PCB v0.8.0 R9 / Radar rail selection and sensing
- (near RAD_C115) RADAR D79 24V / PCB v0.8.0 R9 / Radar rail selection and sensing
- (near RAD_R299) Engineering schematic / sheet 24/31 / release 2.2.4-RC6
- (near R_USB_WAKE) Engineering schematic / sheet 25/31 / release 2.2.4-RC6
- Engineering schematic / sheet 26/31 / release 2.2.4-RC6
- (near RAD_R2) Engineering schematic / sheet 27/31 / release 2.2.4-RC6
- Engineering schematic / sheet 28/31 / release 2.2.4-RC6
- Engineering schematic / sheet 29/31 / release 2.2.4-RC6
- Engineering schematic / sheet 30/31 / release 2.2.4-RC6
- (near RAD_C172) Engineering schematic / sheet 31/31 / release 2.2.4-RC6
- INTER-SHEET ELECTRICAL CONNECTIONS / EXACT NET NAMES
- Each row is an actual Altium wire with a net label. Identical labels electrically join the row to all matching endpoints in the 31 flattened sheets.
- Full component-pad-to-net binding for PCB rerouting: R9_pad_binding.csv in the release verification folder.
- NET
- GND
- 01
- 02
- 03
- 04
- 05
- 06
- 07
- 08
- 09
- 10
- 11
- 12
- 13
- 14
- 15
- 16
- 17
- 18
- 19
- 20
- 21
- 22
- 23
- 24
- 25
- 26
- 27
- 28
- 29
- 30
- 31
- 3V3
- 5V_GNSS
- RADAR_12V
- TI_1V0
- TI_1V0_FILTERED
- TI_1V2
- TI_1V4_APLL
- TI_1V4_SYNTH
- TI_1V8
- TI_1V8_FILTERED
- TI_3V3
- TI_3V3REG_MODE
- TI_3V3REG_VCC
- TI_3V3_VIO
- TI_5V0
- TI_PMICOUT_1V0
- TI_PMICOUT_1V2
- TI_PMICOUT_1V8
- TI_PVIN3V3
- TI_REGOUT_3V3
- VIN_PROTECTED_24V
- CAN_RX
- CAN_TX
- GNSS_PPS
- GNSS_RX_EXT
- GNSS_TX_EXT
- HOST_UART1_RX
- HOST_UART1_TX
- HOST_UART2_RX
- HOST_UART2_TX
- IMU_DRDY
- IMU_MISO
- IMU_MOSI
- IMU_NSS
- IMU_SCK
- RADAR_CANH
- RADAR_CANL
- RAD_CAN_SHDN
- RAD_CAN_STB
- SWDIO
- TI_MSS_MCANA_RX
- TI_MSS_MCANA_TX
- TI_MSS_UARTA_RX
- TI_SOP3_MSS_UARTB_TX
- TI_SOP4_MSS_UARTA_TX
- USB_BRIDGE_RESET_N
- USB_CTS_N
- USB_VBUS
- USB_VBUS_SENSE
- USB_WAKE_N
- TI_+3.3VD
- TI_AGND
- TI_AR_NERROUT
- TI_AR_NRST
- TI_FB_B1
- TI_FB_B2
- TI_FB_B3
- TI_MSS_I2CA_SCL
- TI_MSS_I2CA_SDA
- TI_NERR_MCU
- TI_NetC123_2
- TI_NetC17_1
- TI_NetC17_2
- TI_NetC19_1
- TI_NetC19_2
- TI_NetC1_2
- TI_NetC81_1
- TI_NetC81_2
- TI_NetL1_1
- TI_NetR186_1
- TI_NetR190_2
- TI_NetR193_1
- TI_NetR298_1
- TI_NetR33_1
- TI_NetR35_1
- TI_NetR386_2
- TI_NetR57_1
- TI_NetR58_1
- TI_NetR59_1
- TI_NetR62_1
- TI_NetR63_1
- TI_NetTP8_1
- TI_NRSTOUT
- TI_PMIC_CLK_OUT
- TI_PMIC_EN
- TI_PMIC_NINT
- TI_QSPI_CS
- TI_QSPI_D0
- TI_QSPI_D0_FLASH
- TI_QSPI_D1
- TI_QSPI_D1_FLASH
- TI_QSPI_D2
- TI_QSPI_D2_FLASH
- TI_QSPI_D3
- TI_QSPI_D3_FLASH
- TI_QSPI_SCLK
- TI_QSPI_SCLK_FLASH
- TI_SOP1_MSS_SPIB_CS2
- TI_SW_B1
- TI_SW_B2
- TI_SW_B3
- TI_SYNCCLKIN
- TI_VBGAP
- TI_VPP_1P7
- TI_XTALM
- TI_XTALP
- BOOT0
- BUCK5_SW
- BUCK_SW
- MCU_HSE_25M
- NRST
- RADAR_EFUSE_FLT
- RADAR_REF
- RAD_FRAME_RAW
- SWCLK
- SWO
- SYS_EFUSE_FLT
- U5_PG
- U5_SS_LOCAL
- U6_BGATE
- U6_DRV
- U6_DVDT
- U6_ILIM_LOCAL
- U6_OVP_LOCAL
- U6_PGTH_LOCAL
- U6_UVLO_LOCAL
- U7_DVDT
- U7_ILIM_LOCAL
- U7_OVLO_LOCAL
- U7_UVLO_LOCAL
- U8_BOOT
- U8_ENABLE
- U8_FB_LOCAL
- U8_PGOOD
- U8_RT_LOCAL
- U8_SW
- U8_VCC
- U9_PG
- U9_SS_LOCAL
- V12_SYS
- VCAP1_LOCAL
- VCAP2_LOCAL
- VDDA_FILTERED
- VIN_RAW
- Power
- Interfaces
- GND and other nets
